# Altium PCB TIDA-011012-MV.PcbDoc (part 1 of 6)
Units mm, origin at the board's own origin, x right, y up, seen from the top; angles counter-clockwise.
Board outline 360 x 280 mm, 4 copper layers (Top Layer, Layer 1, Layer 2, Bottom Layer), stack 2.066 mm thick; 566 components, 345 nets, 1738 pads, 2486 vias.
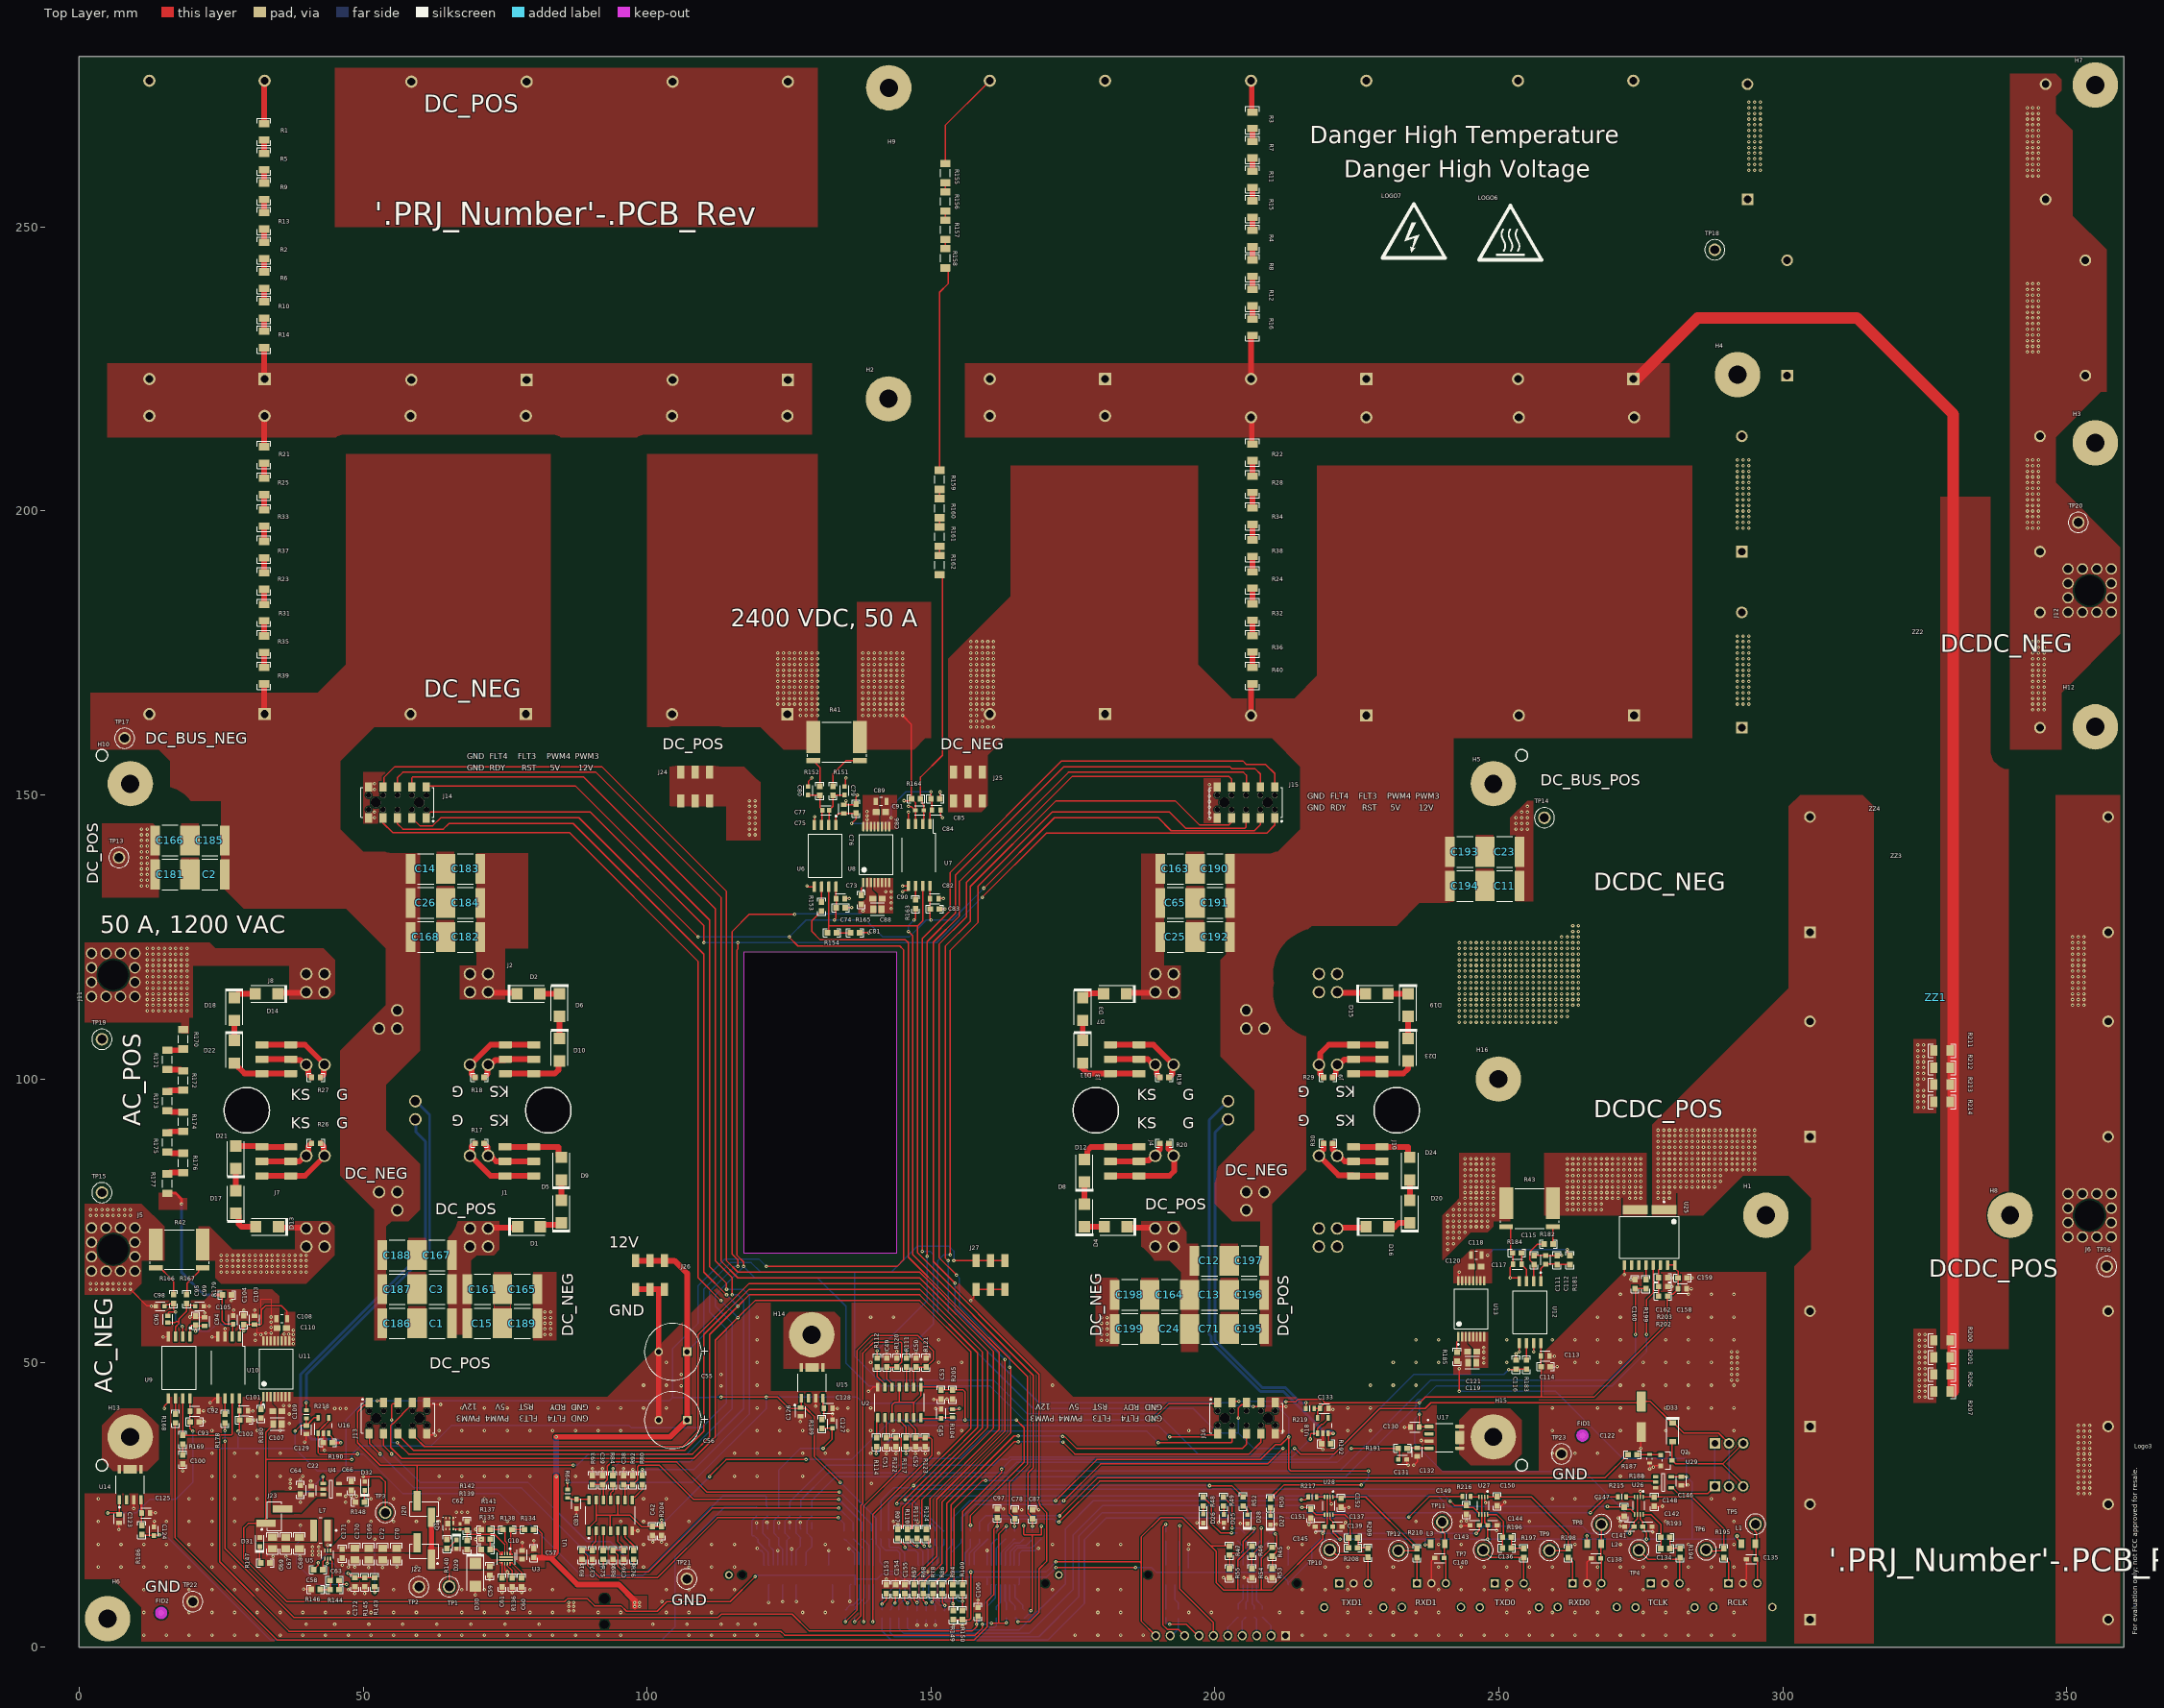
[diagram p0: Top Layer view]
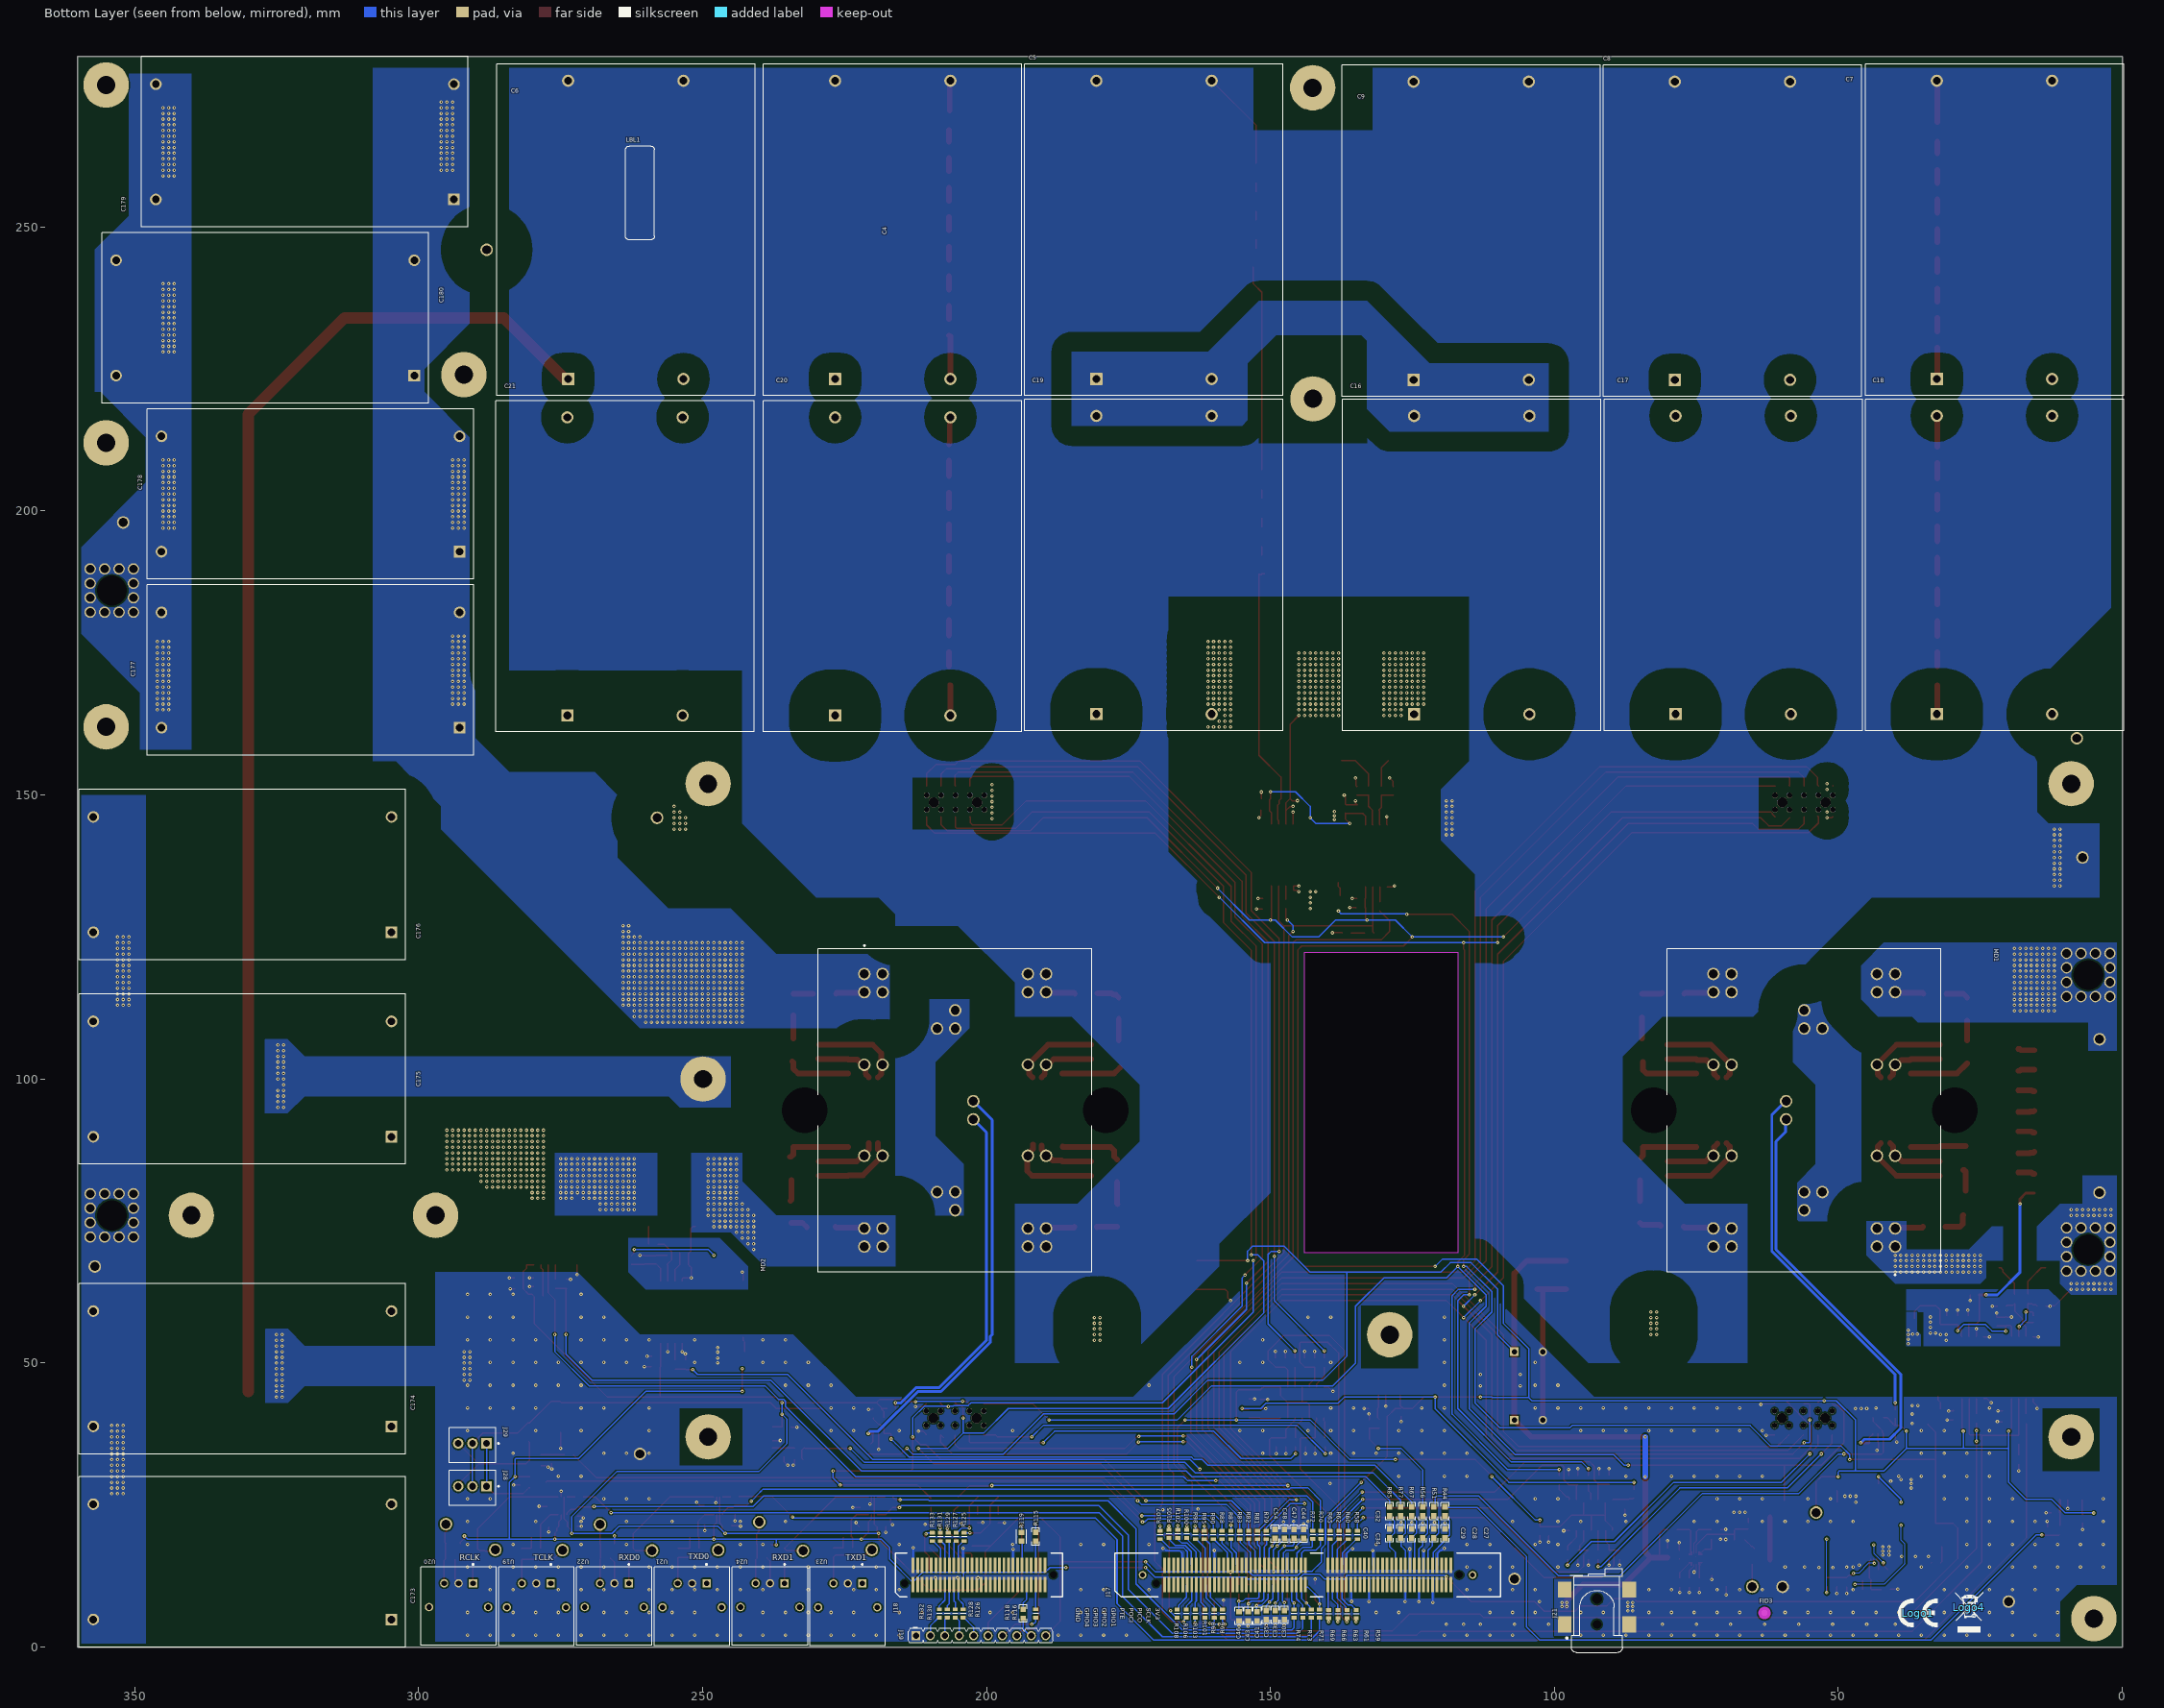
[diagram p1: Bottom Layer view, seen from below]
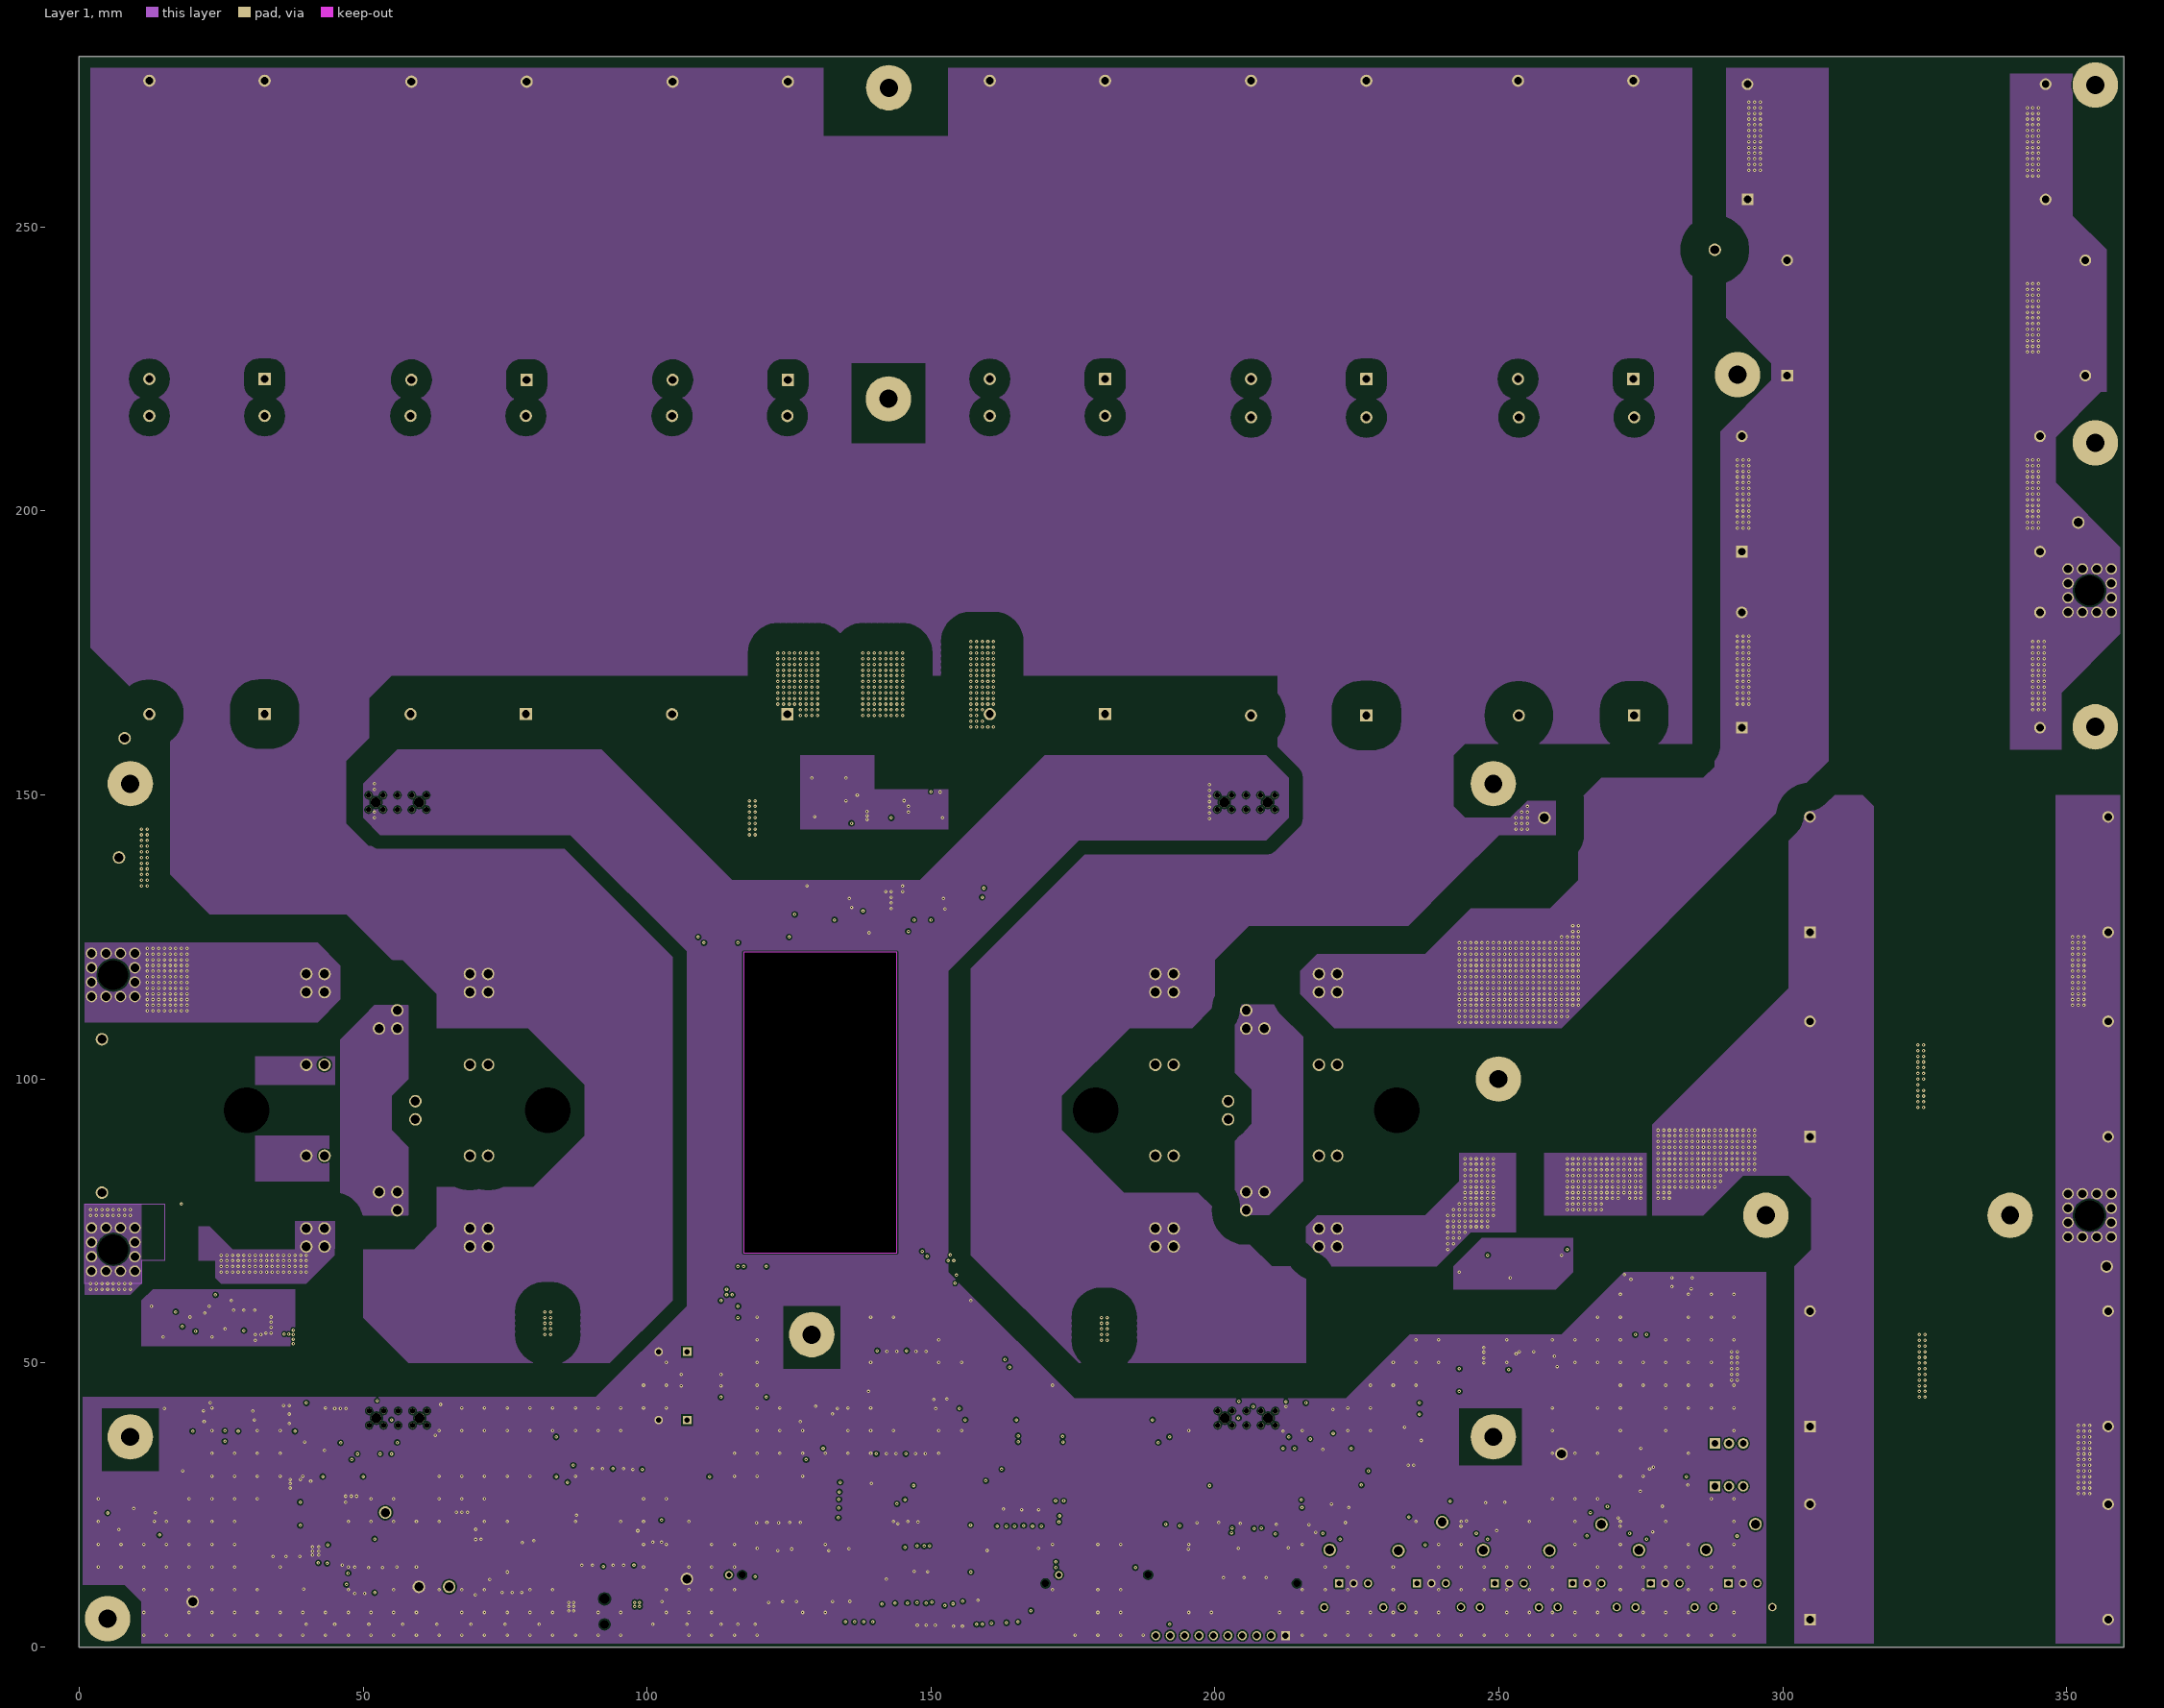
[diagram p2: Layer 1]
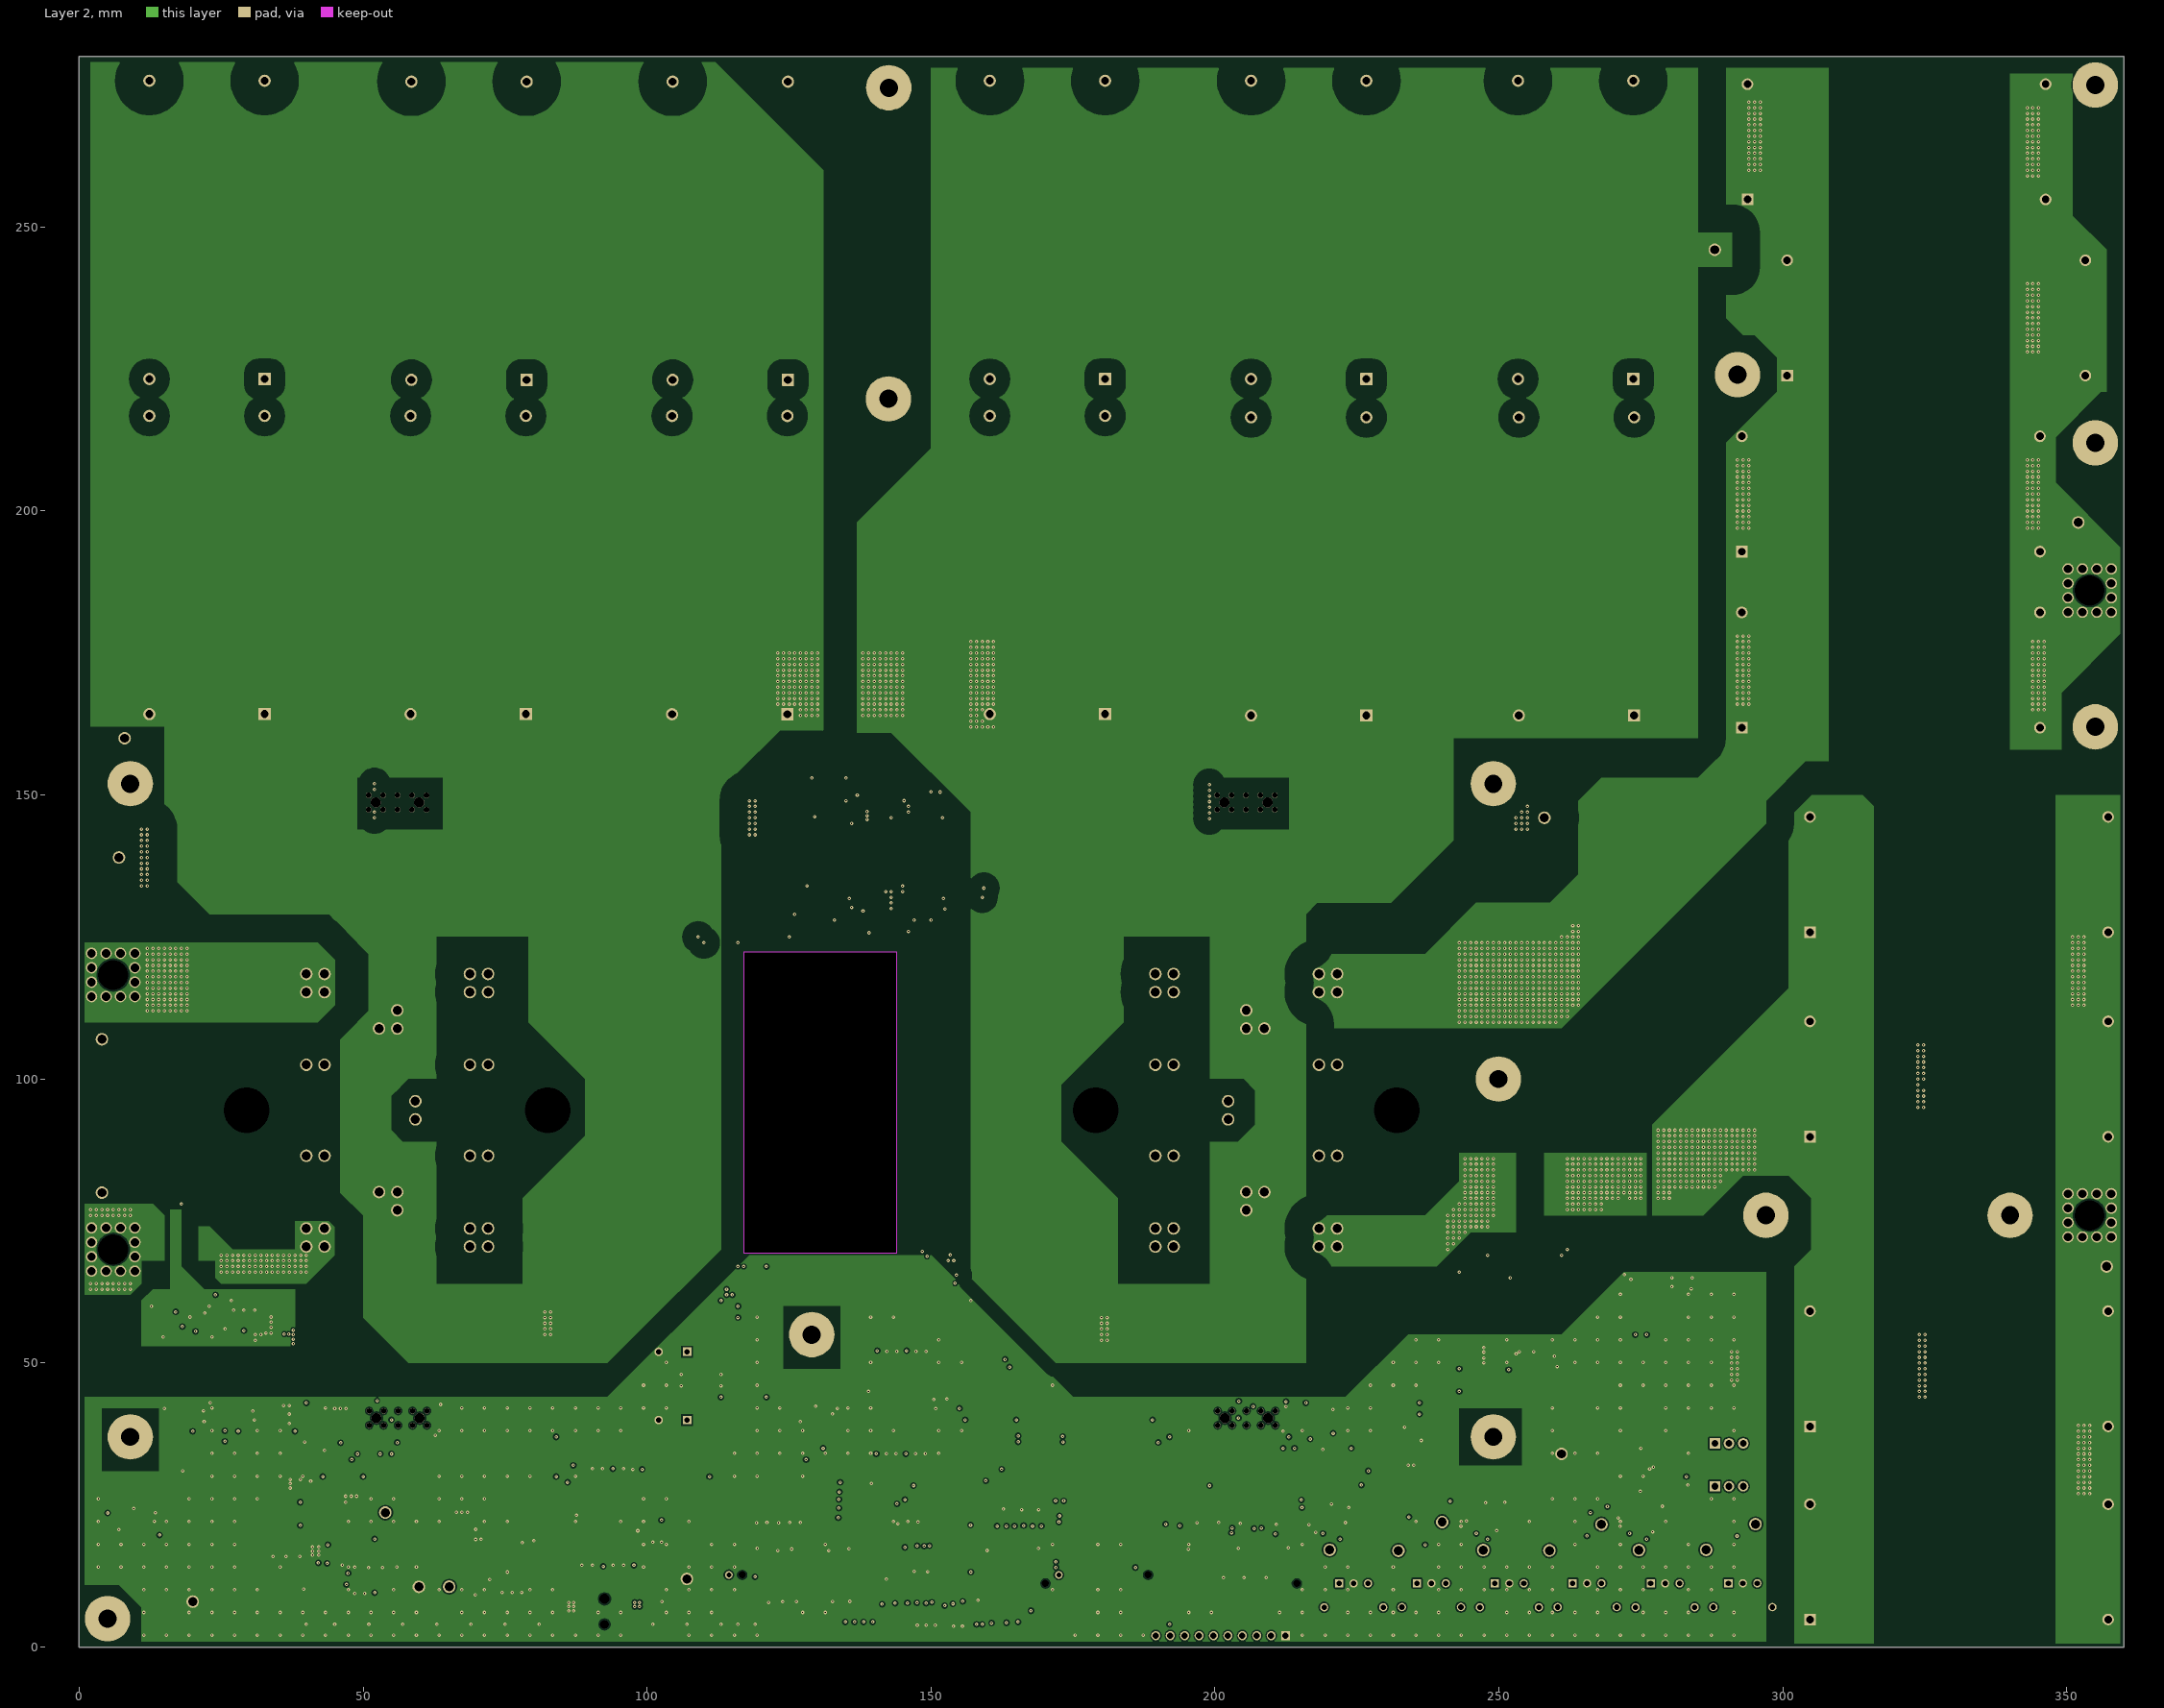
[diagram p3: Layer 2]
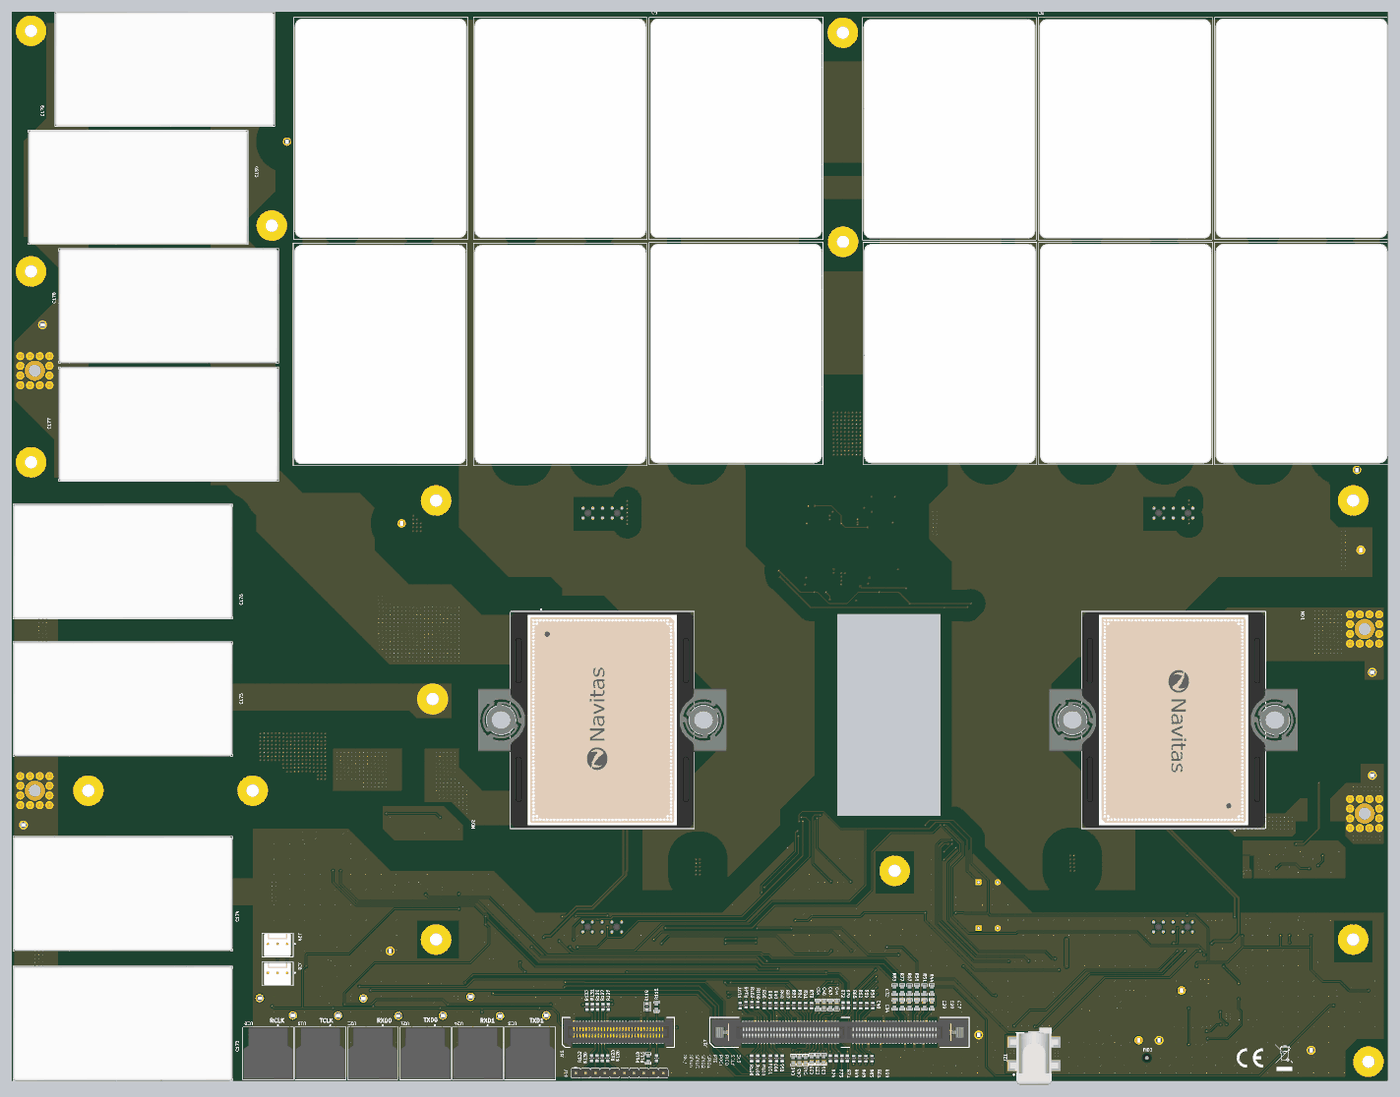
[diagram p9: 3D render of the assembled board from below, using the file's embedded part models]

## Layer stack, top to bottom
Top Solder: solder mask 0.0102, Solder Resist, Dk 3.5
Top Layer: signal copper 0.105
Dielectric 1: prepreg 0.0711, PP-006, Dk 4.1
Layer 1: signal copper 0.105
Dielectric1: core 1.5037, FR-4 High Tg, Dk 4.8
Layer 2: signal copper 0.105
Dielectric 2: prepreg 0.0711, PP-006, Dk 4.1
Bottom Layer: signal copper 0.105
Bottom Solder: solder mask 0.0102, Solder Resist, Dk 3.5

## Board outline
0,0 360,0 360,280 0,280
cut-out: 117,69.4 144,69.4 144,122.3 117,122.3

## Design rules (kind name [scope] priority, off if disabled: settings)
AcuteAngle [All] p1: minimum=4.50000000000000E+0001 checktracksonly=FALSE
AssemblyTestPointUsage [All] p1: valid=2
BoardOutlineClearance BoardOutlineClearance_MountingHoles [OnCopper and InComponentClass('Mounting Holes')] p1: gap=1 ignorepadtopadclearanceinfootprint=FALSE
BoardOutlineClearance BoardOutlineClearance_Poly [OnCopper and IsPoly] p2: gap=0.635 ignorepadtopadclearanceinfootprint=FALSE
BoardOutlineClearance [OnCopper and Not InComponentClass('Logo') and not InComponentClass('FiducialMark') and not InRegion(1000,500,4000,800) and not InPoly] p3: gap=1.016 ignorepadtopadclearanceinfootprint=FALSE
Clearance Clearance_HV_DC_P_OutLayer_A [InNetClass('HV_DC_P') and (OnLayer('Top Layer') or OnLayer('Bottom Layer') or OnLayer('Multi-Layer')) vs (InNetClass('HV_DC_N') OR InNetClass('HV_AC_N') OR InNetClass('HV_AC_P') OR InNetClass('HV_DC_SN_N') OR InNetClass('HV_DC_SN_P') )  and (OnLayer('Top Layer') or OnLayer('Bottom Layer') or OnLayer('Multi-Layer'))] p1: gap=7 ignorepadtopadclearanceinfootprint=TRUE
Clearance Clearance_HVM_OutLayer_A [InNetClass('HVM') and (OnLayer('Top Layer') or OnLayer('Bottom Layer') or OnLayer('Multi-Layer')) vs (InNetClass('HV_DC_N') OR InNetClass('HV_AC_N') OR InNetClass('HV_AC_P') OR InNetClass('HV_DC_SN_N') OR InNetClass('HV_DC_SN_P') OR InNetClass('HV_DC_P') )  and (OnLayer('Top Layer') or OnLayer('Bottom Layer') or OnLayer('Multi-Layer'))] p2: gap=3.5 ignorepadtopadclearanceinfootprint=TRUE
Clearance Clearance_HV_DC_N_OutLayer_A [InNetClass('HV_DC_N') and (OnLayer('Top Layer') or OnLayer('Bottom Layer') or OnLayer('Multi-Layer')) vs (InNetClass('HV_DC_P') OR InNetClass('HV_AC_N') OR InNetClass('HV_AC_P') OR InNetClass('HV_DC_SN_N') OR InNetClass('HV_DC_SN_P'))   and (OnLayer('Top Layer') or OnLayer('Bottom Layer') or OnLayer('Multi-Layer'))] p3: gap=7 ignorepadtopadclearanceinfootprint=TRUE
Clearance Clearance_HV_AC_N_OutLayer_A [InNetClass('HV_AC_N') and  (OnLayer('Top Layer') or OnLayer('Bottom Layer') or OnLayer('Multi-Layer')) vs (InNetClass('HV_DC_N') OR InNetClass('HV_DC_P') OR InNetClass('HV_AC_P') OR InNetClass('HV_DC_SN_N') OR InNetClass('HV_DC_SN_P')  )   and (OnLayer('Top Layer') or OnLayer('Bottom Layer') or OnLayer('Multi-Layer'))] p4: gap=7 ignorepadtopadclearanceinfootprint=TRUE
Clearance Clearance_HV_DC_SN_N_OutLayer_A [InNetClass('HV_DC_SN_N')  and (OnLayer('Top Layer') or OnLayer('Bottom Layer') or OnLayer('Multi-Layer')) vs (InNetClass('HV_DC_N') OR InNetClass('HV_DC_P') OR InNetClass('HV_AC_P') OR InNetClass('HV_AC_N') OR InNetClass('HV_DC_SN_P'))  and (OnLayer('Top Layer') or OnLayer('Bottom Layer') or OnLayer('Multi-Layer'))] p5: gap=7 ignorepadtopadclearanceinfootprint=TRUE
Clearance Clearance_HV_DC_SN_P_OutLayer_A [InNetClass('HV_DC_SN_P')  and (OnLayer('Top Layer') or OnLayer('Bottom Layer') or OnLayer('Multi-Layer')) vs (InNetClass('HV_DC_N') OR InNetClass('HV_DC_P') OR InNetClass('HV_AC_P') OR InNetClass('HV_DC_SN_N') OR InNetClass('HV_AC_N')) and  (OnLayer('Top Layer') or OnLayer('Bottom Layer') or OnLayer('Multi-Layer'))] p6: gap=7 ignorepadtopadclearanceinfootprint=TRUE
Clearance Clearance_HV_AC_P_OutLayer_A [InNetClass('HV_AC_P')       and (OnLayer('Top Layer') or OnLayer('Bottom Layer') or OnLayer('Multi-Layer')) vs (InNetClass('HV_DC_N') OR InNetClass('HV_DC_P') OR InNetClass('HV_AC_N') OR InNetClass('HV_DC_SN_N') OR InNetClass('HV_DC_SN_P'))   and (OnLayer('Top Layer') or OnLayer('Bottom Layer') or OnLayer('Multi-Layer'))] p7: gap=5 ignorepadtopadclearanceinfootprint=TRUE
Clearance Clearance_HV_DC_P_InnerLayers [InNetClass('HV_DC_P') vs InNetClass('HV_DC_N') OR InNetClass('HV_AC_N') OR InNetClass('HV_AC_P') OR InNetClass('HV_DC_SN_N') OR InNetClass('HV_DC_SN_P')] p8: gap=5 ignorepadtopadclearanceinfootprint=TRUE
Clearance Clearance_HVM_InnerLayers [InNetClass('HVM') vs (InNetClass('HV_DC_N') OR InNetClass('HV_AC_N') OR InNetClass('HV_AC_P') OR InNetClass('HV_DC_SN_N') OR InNetClass('HV_DC_SN_P') OR InNetClass('HV_DC_P') )] p9: gap=2.5 ignorepadtopadclearanceinfootprint=TRUE
Clearance Clearance_HV_DC_N_InnerLayers [InNetClass('HV_DC_N') vs InNetClass('HV_DC_P') OR InNetClass('HV_AC_N') OR InNetClass('HV_AC_P') OR InNetClass('HV_DC_SN_N') OR InNetClass('HV_DC_SN_P')] p10: gap=5 ignorepadtopadclearanceinfootprint=TRUE
Clearance Clearance_HV_AC_N_InnerLayers [InNetClass('HV_AC_N') vs InNetClass('HV_DC_N') OR InNetClass('HV_DC_P') OR InNetClass('HV_AC_P') OR InNetClass('HV_DC_SN_N') OR InNetClass('HV_DC_SN_P')] p11: gap=5 ignorepadtopadclearanceinfootprint=TRUE
Clearance Clearance_HV_AC_P_InnerLayers [InNetClass('HV_AC_P') vs InNetClass('HV_DC_N') OR InNetClass('HV_DC_P') OR InNetClass('HV_AC_N') OR InNetClass('HV_DC_SN_N') OR InNetClass('HV_DC_SN_P')] p12: gap=5 ignorepadtopadclearanceinfootprint=TRUE
Clearance Clearance_HV_DC_SN_N_InnerLayers [InNetClass('HV_DC_SN_N') vs InNetClass('HV_DC_N') OR InNetClass('HV_DC_P') OR InNetClass('HV_AC_P') OR InNetClass('HV_AC_N') OR InNetClass('HV_DC_SN_P')] p13: gap=5 ignorepadtopadclearanceinfootprint=TRUE
Clearance Clearance_HV_DC_SN_P_InnerLayers [InNetClass('HV_DC_SN_P') vs InNetClass('HV_DC_N') OR InNetClass('HV_DC_P') OR InNetClass('HV_AC_P') OR InNetClass('HV_DC_SN_N') OR InNetClass('HV_AC_N')] p14: gap=5 ignorepadtopadclearanceinfootprint=TRUE
Clearance Clearance_Keepouts [((IsTrack Or IsArc) And Not InPoly) And IsFree and IsKeepOut vs ((IsTrack Or IsArc) And Not InPoly) And IsFree and IsKeepOut] p15: gap=0 ignorepadtopadclearanceinfootprint=FALSE
Clearance Clearance_Poly [InPolygon] p16: gap=0.254 ignorepadtopadclearanceinfootprint=TRUE
Clearance Clearance_FiducialMark [IsKeepOut and InComponentClass('FiducialMark') vs IsPad and InComponentClass('FiducialMark')] p17: gap=0 ignorepadtopadclearanceinfootprint=FALSE
Clearance [All] p18: gap=0.2 ignorepadtopadclearanceinfootprint=TRUE
ComponentClearance ComponentClearance_MountingHoles_FiducialMarks [InComponentClass('Mounting Holes') vs InComponentClass('FiducialMark')] p1: gap=1.27 collisioncheckmode=3 verticalgap=0.254 showdistances=FALSE
ComponentClearance ComponentClearance_Shunt [InComponentClass('Header') vs InComponentClass('Shunt')] p2: gap=0 collisioncheckmode=3 verticalgap=0 showdistances=FALSE
ComponentClearance ComponentClearance_Logo [InComponentClass('Logo')] p3: gap=0.762 collisioncheckmode=3 verticalgap=0.254 showdistances=FALSE
ComponentClearance ComponentClearance_ScrewToNut [(HasFootprint('NY PMS 440 0025 PH')) vs (HasFootprint('Keystone_1902C'))] p4: gap=0.127 collisioncheckmode=3 verticalgap=0.254 showdistances=FALSE
ComponentClearance ComponentClearance_MountingHoles [InComponentClass('Mounting Holes')] p5: gap=2 collisioncheckmode=3 verticalgap=2540 showdistances=FALSE
ComponentClearance ComponentClearance_SmallPassives [HasFootprint('0201*') or HasFootprint('0402*') or HasFootprint('0508') or HasFootprint('0603*') or HasFootprint('0612') or HasFootprint('0805*') or HasFootprint('0815*') or HasFootprint('0830*') or HasFootprint('1206*') or HasFootprint('1210*') or HasFootprint('1808*') or HasFootprint('1812*') or HasFootprint('1825*') or HasFootprint('2010*') or HasFootprint('2220*') or HasFootprint('2225*') or HasFootprint('2512*') or HasFootprint('2728*') or HasFootprint('3518*') vs HasFootprint('0201*') or HasFootprint('0402*') or HasFootprint('0508') or HasFootprint('0603*') or HasFootprint('0612') or HasFootprint('0805*') or HasFootprint('0815*') or HasFootprint('0830*') or HasFootprint('1206*') or HasFootprint('1210*') or HasFootprint('1808*') or HasFootprint('1812*') or HasFootprint('1825*') or HasFootprint('2010*') or HasFootprint('2220*') or HasFootprint('2225*') or HasFootprint('2512*') or HasFootprint('2728*') or HasFootprint('3518*')] p6: gap=0.38 collisioncheckmode=3 verticalgap=0.254 showdistances=FALSE
ComponentClearance ComponentClearance_THtoSMT [IsThruComponent vs IsSMTComponent] p7: gap=0.762 collisioncheckmode=3 verticalgap=0.762 showdistances=FALSE
ComponentClearance ComponentClearance_THtoTH [IsThruComponent vs IsThruComponent] p8: gap=0.508 collisioncheckmode=3 verticalgap=0.762 showdistances=FALSE
ComponentClearance [All] p9: gap=0.508 collisioncheckmode=3 verticalgap=0.254 showdistances=FALSE
DiffPairsRouting [All] p1: maxlimit=2.54 minlimit=0.254 mostfreqgap=0.254 toplayer_minwidth=0.381 toplayer_maxwidth=0.381 toplayer_prefwidth=0.381 midlayer1_minwidth=0.381 midlayer1_maxwidth=0.381 midlayer1_prefwidth=0.381 midlayer2_minwidth=0.381 midlayer2_maxwidth=0.381 midlayer2_prefwidth=0.381 bottomlayer_minwidth=0.381 bottomlayer_maxwidth=0.381 bottomlayer_prefwidth=0.381 maxuncoupledlength=25.4
FabricationTestPointUsage TestPointUsage [All] p1: valid=2 allowmultiple=FALSE
FabricationTestpoint Testpoint [All] p1: side=3 testpointundercomponent=TRUE minsize=1.016 maxsize=2.54 preferedsize=1.524 minholesize=0 maxholesize=1.016 preferedholesize=0.813 testpointgrid=0.025 allowsidetop=TRUE allowsidebottom=TRUE usegrid=TRUE gridtolerance=0
FanoutControl Fanout_LCC [IsLCC] p1: bgadir=Out bgaviamode=Centered fanoutstyle=Auto fanoutdirection=Alternating viagrid=0.025 // Fanout_LCC (Default Rule)
FanoutControl Fanout_BGA [IsBGA] p2: bgadir=Out bgaviamode=Centered fanoutstyle=Auto fanoutdirection=Alternating viagrid=0.025 // Fanout_BGA (Default Rule)
FanoutControl Fanout_Default [All] p4: bgadir=Out bgaviamode=Centered fanoutstyle=Auto fanoutdirection=Alternating viagrid=0.025 // Fanout_Default (Default Rule)
FanoutControl Fanout_Small [(CompPinCount < 5)] p5: bgadir=Out bgaviamode=Centered fanoutstyle=Auto fanoutdirection=OutThenIn viagrid=0.025 // Fanout_Small (Default Rule)
HoleSize [All] p1: absolutevalues=TRUE maxlimit=6.375 minlimit=0.2 maxpercent=80.000 minpercent=20.000
MinimumAnnularRing MinimumAnnularRing_ThermalPadVias [IsVia and InAnyComponent] p1: minimumring=0.15
MinimumAnnularRing [All] p2: minimumring=0.2
MinimumSolderMaskSliver MinimumSolderMaskSliver_Logo [InComponentClass('Logo') vs InComponentClass('Logo')] p1: minsoldermaskwidth=0.018
MinimumSolderMaskSliver [All] p2: minsoldermaskwidth=0.1
PlaneConnect [All] p1: planeconnectstyle=Relief reliefexpansion=0.254 reliefentries=4 reliefconductorwidth=0.254 reliefairgap=0.254
PolygonConnect [All] p1: connectstyle=Direct reliefconductorwidth=0.254 reliefentries=4 polygonreliefangle="90 Angle" airgapwidth=0.254
RoutingLayers [All] p1: top layer_v5=TRUE mid layer 1_v5=FALSE mid layer 2_v5=FALSE bottom layer_v5=TRUE
RoutingVias ThermalPadVias [IsVia and InAnyComponent] p1: holewidth=0.2 width=0.5 viastyle="Through Hole" minholewidth=0.2 minwidth=0.5 maxholewidth=0.33 maxwidth=0.6
RoutingVias [All] p2: holewidth=0.406 width=0.864 viastyle="Through Hole" minholewidth=0.2 minwidth=0.61 maxholewidth=1.016 maxwidth=1.651 useviatemplates=TRUE viatemplateguid#1={116764BD-FC13-4FEF-98DC-B798B7858576} viatemplatename#1=v60h20m0mx0
SilkToBoardRegionClearance [Not ((IsComment or IsDesignator) And (Hide <> 'False')) and not InRegion(1000,500,4000,800)] p1:
SilkToSilkClearance SilkToSilkClearance_Pb-FreeLogo [(HasFootprint('Pb-Free_Overlay_Medium') OR HasFootprint('Pb-Free_Overlay_Small')) vs (HasFootprint('Pb-Free_Overlay_Medium') OR HasFootprint('Pb-Free_Overlay_Small'))] p1: silktosilkclearance=0
SilkToSilkClearance [All] p2: silktosilkclearance=0.1
SilkToSolderMaskClearance SilkToComponentPadClearance [(IsPad or IsFill or IsRegion) and InAnycomponent] p1: minsilkscreentomaskgap=0.127 clearancetoexposedcopper=TRUE
SilkToSolderMaskClearance "Silk to Solder Mask Opening" [All] p2: minsilkscreentomaskgap=0.1 clearancetoexposedcopper=FALSE
SolderMaskExpansion [All] p1: expansion=0.05 istentingtop=FALSE
UnRoutedNet [All] p1: checkbadconnections=TRUE
Width [All] p1: maxlimit=5 minlimit=0.2 preferedwidth=0.254 checkconnectedcopper=TRUE
13 further rules are at their usual default settings.

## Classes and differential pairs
net class HVM: 3V3 5V 12V 12V_FET_DRAIN 12V_IN 12V_OUT AC_BUF_PMW1 AC_BUF_PMW2 AC_BUF_PMW3 AC_BUF_PMW4 AC_FAULT_FET1 AC_FAULT_FET2 AC_FAULT_FET3 AC_FAULT_FET4 AC_GD_RDY AC_GD_RST/EN AC_PWM1 AC_PWM2 AC_PWM3 AC_PWM4 CLK_MOD_AC CLK_MOD_DC DATA_I_AC DATA_I_DC DATA_V_AC DATA_V_DC DC_BUF_PMW1 DC_BUF_PMW2 DC_BUF_PMW3 DC_BUF_PMW4 DC_FAULT_FET1 DC_FAULT_FET2 DC_FAULT_FET3 DC_FAULT_FET4 DC_GD_RDY DC_GD_RST/EN DC_OC DC_OC_CMP DC_PWM1 DC_PWM2 DC_PWM3 DC_PWM4 DEBUG_GPIO1 DEBUG_GPIO2 DEBUG_GPIO3 DEBUG_GPIO4 EF_dVdt EF_EN EF_ILIM EF_ITIMER EF_OVLO EF_PG EF_PGTH FAN_EN FAN_PWM FSIRXA_CLK FSIRXA_D0 FSITXA_CLK FSITXA_D0 GND I_HALL ID1 ID2 ID3 LED_GREEN LED_RED NetC4_1 NetC22_1 NetC27_1 NetC28_1 NetC29_1 NetC30_1 NetC31_2 NetC32_1 NetC33_1 NetC34_1 NetC35_1 NetC40_1 NetC41_1 NetC43_1 NetC44_1 NetC45_2 NetC46_1 NetC47_1 NetC48_1 NetC54_1 NetC58_1 NetC58_2 NetC63_2 NetC70_1 NetC81_1 NetC100_1 NetC125_1 NetC128_1 NetC132_1 NetC134_1 NetC135_2 NetC136_1 NetC138_2 NetC139_1 NetC140_2 NetC153_1 NetC154_1 NetC155_1 NetC162_1 NetC172_1 NetD25_2 NetD26_2 NetD27_2 NetD28_2 NetD29_1 NetD31_1 NetD32_1 NetD33_2 NetH13_1 NetH14_1 NetH15_1 NetH16_1 NetJ17_3 NetJ17_4 NetJ17_5 NetJ17_6 NetJ17_8 NetJ17_12 NetJ17_14 NetJ17_18 NetJ17_20 NetJ17_23 NetJ17_24 NetJ17_26 NetJ17_27 NetJ17_28 NetJ17_29 NetJ17_30 NetJ17_31 NetJ17_32 NetJ17_33 NetJ17_34 NetJ17_36 NetJ17_37 NetJ17_39 NetJ17_40 NetJ17_41 NetJ17_42 NetJ17_43 NetJ17_44 NetJ17_45 NetJ17_49 NetJ17_50 NetJ17_51 NetJ17_52 NetJ17_53 NetJ17_54 NetJ17_55 NetJ17_56 NetJ17_57 NetJ17_59 NetJ17_61 NetJ17_62 NetJ17_63 NetJ17_66 NetJ17_75 NetJ17_77 NetJ17_79 NetJ17_80 NetJ17_81 NetJ17_82 NetJ17_85 NetJ17_86 NetJ17_87 NetJ17_88 NetJ17_89 NetJ17_90 NetJ17_91 NetJ17_92 NetJ17_93 NetJ17_94 NetJ17_95 NetJ17_96 NetJ17_99 NetJ17_100 NetJ17_101 NetJ17_102 NetJ17_103 NetJ17_104 NetJ17_105 NetJ17_106 NetJ17_107 NetJ17_108 NetJ17_109 NetJ17_110 NetJ17_113 NetJ17_114 NetJ17_115 NetJ17_116 NetJ17_117 NetJ17_118 NetJ17_119 NetJ17_120 NetJ18_121 NetJ18_122 NetJ18_123 NetJ18_124 NetJ18_125 NetJ18_126 NetJ18_127 NetJ18_128 NetJ18_129 NetJ18_130 NetJ18_131 NetJ18_132 NetJ18_133 NetJ18_134 NetJ18_136 NetJ18_137 NetJ18_138 NetJ18_139 NetJ18_140 NetJ18_141 NetJ18_142 NetJ18_143 NetJ18_144 NetJ18_145 NetJ18_146 NetJ18_147 NetJ18_148 NetJ18_149 NetJ18_150 NetJ18_151 NetJ18_152 NetJ18_153 NetJ18_154 NetJ18_155 NetJ18_156 NetJ18_159 NetJ18_160 NetJ18_161 NetJ18_162 NetJ18_163 NetJ18_164 NetJ18_165 NetJ18_166 NetJ18_167 NetJ18_168 NetJ18_169 NetJ18_170 NetJ18_171 NetJ18_172 NetJ18_173 NetJ18_174 NetJ18_175 NetJ18_176 NetJ18_177 NetJ18_178 NetJ28_1 NetQ2_1 NetR75_1 NetR76_1 NetR80_1 NetR84_1 NetR111_1 NetR112_1 NetR114_1 NetR117_1 NetR153_1 NetR163_1 NetR165_1 NetR168_1 NetR178_1 NetR180_1 NetR183_1 NetR185_1 NetR194_2 NetR195_1 NetR197_2 NetR198_1 NetR199_1 NetR209_2 NetR210_1 NetR215_2 NetR216_2 NetR217_2 NetU19_4 NetU19_5 NetU20_4 NetU20_5 NetU21_4 NetU21_5 NetU22_4 NetU22_5 NetU23_4 NetU23_5 NetU24_4 NetU24_5 NetU25_4 NetU25_5 NTC1_N NTC1_P NTC2_N NTC2_P PWM_BUF_EN PWM_CLK_SD_AC_DELAYED PWM_CLK_SD_DC_DELAYED PWM_SYNC_RX PWM_SYNC_TX RXCLK_5V RXD0_5V RXD1_5V SPIB_CLK SPIB_PICO SPIB_POCI SPIB_PTE TEMP1 TEMP2 TEMP3 TEMP4 TEMP5 TXCLK_5V TXD0_5V TXD1_5V
net class HV_DC_SN_N: DC_DS1 DC_G1 DC_KS1 NetC177_1 NetC177_2
net class HV_AC_P: AC_DS3 AC_G3 AC_KS3 VAC_POS
net class HV_AC_N: 5V_ISO_AC_SENS AC_DS1 AC_G1 AC_KS1 GND_ISO_AC_SENS IAC_NEG IAC_POS NetC96_1 NetC96_2 NetC105_2 NetD13_1
net class HV_DC_SN_P: 5V_ISO_SN_SENS DC_DS3 DC_G3 DC_KS3 I_HALL_N I_HALL_P I_SW_NEG I_SW_POS NetC111_1 NetC115_1 NetC117_1 NetC173_2 NetD16_1
net class HV_DC_P: DC_BUS_POS
net class HV_DC_N: AC_DS2 AC_G2 AC_G4 AC_KS2 AC_KS4 DC_BUS_DAB DC_BUS_NEG DC_DS2 DC_DS4 DC_G2 DC_G4 DC_KS2 DC_KS4 NetD22_2
component class "U_TIDA-011012 Switch Node Hall Current Sensing": C158 C159 C160 C162 R199 R202 R203 U25
component class "U_TIDA-011012 DC IV Sensing": C73 C74 C75 C76 C77 C78 C79 C80 C81 C82 C83 C84 C85 C86 C87 C88 C89 C90 C91 R151 R152 R153 R154 R155 R156 R157 R158 R159 R160 R161 R162 R163 R164 R165 U6 U7 U8
component class U_TIDA-011012_Hardware: !PCB1 FID1 FID2 FID3 H1 H2 H3 H4 H5 H6 H7 H8 H9 H10 H12 LBL1 Logo1 Logo3 Logo4 LOGO6 LOGO7 ZZ1 ZZ2 ZZ3 ZZ4
component class Label: LBL1
component class FiducialMark: FID1 FID2 FID3
component class AssemblyNote: ZZ1 ZZ2 ZZ3 ZZ4
component class "U_TIDA-011012 Optical Interface": C134 C135 C136 C137 C138 C139 C140 C141 C142 C143 C144 C145 C147 C148 C149 C150 C151 C152 L1 L2 L3 R193 R194 R195 R196 R197 R198 R208 R209 R210 R215 R216 R217 TP4 TP5 TP6 TP7 TP8 TP9 TP10 TP11 TP12 U19 U20 U21 U22 U23 U24 U26 U27 U28
component class "U_TIDA-011012 Fans and Temp Sense": C122 C123 C124 C125 C126 C127 C128 C129 C130 C131 C132 C133 C146 D33 H13 H14 H15 J28 J29 Q2 R186 R187 R188 R189 R190 R191 R192 R218 R219 U14 U15 U16 U17 U18 U29
component class "U_TIDA-011012 AC IV Sensing": C92 C93 C94 C95 C96 C97 C98 C99 C100 C101 C102 C103 C104 C105 C106 C107 C108 C109 C110 R166 R167 R168 R169 R170 R171 R172 R173 R174 R175 R176 R177 R178 R179 R180 U9 U10 U11
component class "U_TIDA-011012 Communication": C27 C28 C29 C30 C31 C32 C33 C34 C35 C36 C37 C38 C39 C40 C41 C42 C43 C44 C45 C46 C47 C48 C49 C50 C51 C52 C53 C54 C153 C154 C155 D25 D26 D27 D28 J17 J18 J19 R44 R45 R46 R47 R48 R49 R50 R51 R52 R53 R54 R55 R56 R57 R58 R59 R60 R61 R62 R63 R64 R65 R66 R67 R68 R69 R70 R71 R72 R73 R74 R75 R76 R77 R78 R79 R80 R81 R82 R83 R84 R85 R86 R87 R88 R89 R90 R91 R92 R93 R94 R95 R96 R97 R98 R99 R100 R101 R102 R103 R104 R105 R106 R107 R108 R109 R110 R111 R112 R113 R114 R115 R116 R117 R118 R119 R120 R121 R122 R123 R124 R125 R126 R127 R128 R129 R130 R131 R132 R133 R149 R150 R204 R205 U1 U2
component class "U_TIDA-011012 Current Comparator": C111 C112 C113 C114 C115 C116 C117 C118 C119 C120 C121 R181 R182 R183 R184 R185 U12 U13
component class "TIDA-011012-MV Power Conversion": C1 C2 C3 C4 C5 C6 C7 C8 C9 C11 C12 C13 C14 C15 C16 C17 C18 C19 C20 C21 C23 C24 C25 C26 C65 C71 C161 C163 C164 C165 C166 C167 C168 C173 C174 C175 C176 C177 C178 C179 C180 C181 C182 C183 C184 C185 C186 C187 C188 C189 C190 C191 C192 C193 C194 C195 C196 C197 C198 C199 D1 D2 D3 D4 D5 D6 D7 D8 D9 D10 D11 D12 D13 D14 D15 D16 D17 D18 D19 D20 D21 D22 D23 D24 H16 J1 J2 J3 J4 J5 J6 J7 J8 J9 J10 J11 J12 J13 J14 J15 J16 MD1 MD2 R1 R2 R3 R4 R5 R6 R7 R8 R9 R10 R11 R12 R13 R14 R15 R16 R17 R18 R19 R20 R21 R22 R23 R24 R25 R26 R27 R28 R29 R30 R31 R32 R33 R34 R35 R36 R37 R38 R39 R40 R41 R42 R43 R200 R201 R206 R207 R211 R212 R213 R214 TP13 TP14 TP15 TP16 TP17 TP18 TP19 TP20
component class Header: J19 J20 J22 J23
component class "U_TIDA-011012 Auxiliary Power": C10 C22 C55 C56 C57 C58 C59 C60 C61 C62 C63 C64 C66 C67 C68 C69 C70 C72 C169 C170 C171 C172 D29 D30 D31 D32 J20 J21 J22 J23 J24 J25 J26 J27 L7 Q1 R134 R135 R136 R137 R138 R139 R140 R141 R142 R143 R144 R145 R146 R147 R148 TP1 TP2 TP3 TP21 TP22 TP23 U3 U4 U5
component class "Mounting Holes": H1 H2 H3 H4 H5 H6 H7 H8 H9 H10 H12 H13 H14 H15 H16

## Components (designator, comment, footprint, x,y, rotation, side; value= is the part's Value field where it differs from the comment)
C1 "C2220X103KHRAC7800" FP-C2220X103KHRAC7800_2220-MFG 63,57 r0 top value=10nF
C2 "C2220X103KHRAC7800" FP-C2220X103KHRAC7800_2220-MFG 23,136 r180 top value=10nF
C3 "C2220X103KHRAC7800" FP-C2220X103KHRAC7800_2220-MFG 63,63 r0 top value=10nF
C4 "C4AQPEW5450M3BJ" FP-C4AQPEW5450M3BJ_RADIAL-MFG 216.5,249.5 r90 bottom locked value=45µF
C5 "C4AQPEW5450M3BJ" FP-C4AQPEW5450M3BJ_RADIAL-MFG 170.5,249.5 r90 bottom value=45µF
C6 "C4AQPEW5450M3BJ" FP-C4AQPEW5450M3BJ_RADIAL-MFG 263.5,249.5 r90 bottom locked value=45µF
C7 "C4AQPEW5450M3BJ" FP-C4AQPEW5450M3BJ_RADIAL-MFG 22.5,249.5 r90 bottom locked value=45µF
C8 "C4AQPEW5450M3BJ" FP-C4AQPEW5450M3BJ_RADIAL-MFG 68.65,249.35 r90 bottom locked value=45µF
C9 "C4AQPEW5450M3BJ" FP-C4AQPEW5450M3BJ_RADIAL-MFG 114.65,249.35 r90 bottom locked value=45µF
C10 "CL10B104KA8VPJC" FP-CL10B104KA8VPJC_0603-MFG 78,16.245 r90 top value=100nF
C11 "C2220X103KHRAC7800" FP-C2220X103KHRAC7800_2220-MFG 251,134 r0 top value=10nF
C12 "C2220X103KHRAC7800" FP-C2220X103KHRAC7800_2220-MFG 199,68 r180 top value=10nF
C13 "C2220X103KHRAC7800" FP-C2220X103KHRAC7800_2220-MFG 199,62 r180 top value=10nF
C14 "C2220X103KHRAC7800" FP-C2220X103KHRAC7800_2220-MFG 61,137 r0 top value=10nF
C15 "C2220X103KHRAC7800" FP-C2220X103KHRAC7800_2220-MFG 71,57 r180 top value=10nF
C16 "C4AQPEW5450M3BJ" FP-C4AQPEW5450M3BJ_RADIAL-MFG 114.542,190.483 r90 bottom locked value=45µF
C17 "C4AQPEW5450M3BJ" FP-C4AQPEW5450M3BJ_RADIAL-MFG 68.5,190.5 r90 bottom locked value=45µF
C18 "C4AQPEW5450M3BJ" FP-C4AQPEW5450M3BJ_RADIAL-MFG 22.5,190.5 r90 bottom locked value=45µF
C19 "C4AQPEW5450M3BJ" FP-C4AQPEW5450M3BJ_RADIAL-MFG 170.5,190.5 r90 bottom value=45µF
C20 "C4AQPEW5450M3BJ" FP-C4AQPEW5450M3BJ_RADIAL-MFG 216.5,190.25 r90 bottom locked value=45µF
C21 "C4AQPEW5450M3BJ" FP-C4AQPEW5450M3BJ_RADIAL-MFG 263.65,190.25 r90 bottom locked value=45µF
C22 "CL10B104KA8VPJC" FP-CL10B104KA8VPJC_0603-MFG 40.844,27.576 r90 top value=100nF
C23 "C2220X103KHRAC7800" FP-C2220X103KHRAC7800_2220-MFG 251,140 r0 top value=10nF
C24 "C2220X103KHRAC7800" FP-C2220X103KHRAC7800_2220-MFG 192,56 r0 top value=10nF
C25 "C2220X103KHRAC7800" FP-C2220X103KHRAC7800_2220-MFG 193,125 r180 top value=10nF
C26 "C2220X103KHRAC7800" FP-C2220X103KHRAC7800_2220-MFG 61,131 r0 top value=10nF
C27 "C0603X221K5RACTU" 0603 119.25,20 r90 bottom value=220pF
C28 "C0603X221K5RACTU" 0603 121.2,20 r90 bottom value=220pF
C29 "C0603X221K5RACTU" 0603 123.15,20 r90 bottom value=220pF
C30 "C0603X221K5RACTU" 0603 147.522,5.621 r270 bottom value=220pF
C31 "GMC10X7R104K25NT" FP-GMC10X7R104K25NT_0603-MFG 87.546,25.184 r90 top value=100nF
C32 "C0603X221K5RACTU" 0603 125.1,20 r90 bottom value=220pF
C33 "C0603X221K5RACTU" 0603 149.122,5.621 r270 bottom value=220pF
C34 "C0603X221K5RACTU" 0603 127.05,20 r90 bottom value=220pF
C35 "C0603X221K5RACTU" 0603 150.722,5.621 r270 bottom value=220pF
C36 "C0603X221K5RACTU" 0603 95.844,16.234 r90 top value=220pF
C37 "C0603X221K5RACTU" 0603 90.392,16.234 r90 top value=220pF
C38 "C0603X221K5RACTU" 0603 95.842,29.384 r270 top value=220pF
C39 "C0603X221K5RACTU" 0603 92.176,29.409 r270 top value=220pF
C40 "C0603X221K5RACTU" 0603 129,20 r90 bottom value=220pF
C41 "C0603X221K5RACTU" 0603 152.322,5.421 r270 bottom value=220pF
C42 "C0603X221K5RACTU" 0603 100.962,20.432 r90 top value=220pF
C43 "C0603X221K5RACTU" 0603 153.922,5.421 r270 bottom value=220pF
C44 "C0603X221K5RACTU" 0603 144.164,19.898 r90 bottom value=220pF
C45 "GMC10X7R104K25NT" FP-GMC10X7R104K25NT_0603-MFG 151.773,41.075 r270 top value=100nF
C46 "C0603X221K5RACTU" 0603 155.522,5.421 r270 bottom value=220pF
C47 "C0603X221K5RACTU" 0603 145.836,19.898 r90 bottom value=220pF
C48 "C0603X221K5RACTU" 0603 147.508,19.898 r90 bottom value=220pF
C49 "C0603X221K5RACTU" 0603 142.233,50.075 r270 top value=220pF
C50 "C0603X221K5RACTU" 0603 147.387,50.075 r270 top value=220pF
C51 "C0603X221K5RACTU" 0603 142.117,36.075 r90 top value=220pF
C52 "C0603X221K5RACTU" 0603 147.271,36.075 r90 top value=220pF
C53 "C0603X221K5RACTU" 0603 151.773,44.458 r90 top value=220pF
C54 "C0603X221K5RACTU" 0603 149.18,19.898 r90 bottom value=220pF
C55 "16ZLJ1000MCE10X16" CAPPR5-10x16 104.537,51.989 r180 top value=1000uF
C56 "16ZLJ1000MCE10X16" CAPPR5-10x16 104.537,39.966 r180 top value=1000uF
C57 "C1608X7R1V105K080AC" 0603 80.071,16.574 r90 top value=1uF
C58 "06033C104JAT2A" 0603 42.109,13.62 r180 top value=0.1uF
C59 "C1608X7R1V105K080AC" 0603 72.303,13.443 r270 top value=1uF
C60 "GRM188R72A272KA01D" 0603 77.897,11.376 r270 top value=2700pF
C61 "C0603X332K5RACTU" 0603 74.46,11.361 r270 top value=3300pF
C62 "GRM155R71E104KE14D" 0402L 67.071,21.214 r90 top value=0.1uF
C63 "GRM1885C2A220JA01D" 0603 44.943,11.748 r180 top value=22pF
C64 "EMK107BB7225KA-T" 0603 38.943,27.665 r90 top value=2.2uF
C65 "C2220X103KHRAC7800" FP-C2220X103KHRAC7800_2220-MFG 193,131 r180 top value=10nF
C66 "EMK107BB7225KA-T" 0603 47.895,28.356 r270 top value=2.2uF
C67 "GRM21BZ71A226ME15L" 0805_HV 36.375,18.281 r270 top value=22uF
C68 "GRM21BZ71A226ME15L" 0805_HV 38.781,18.281 r270 top value=22uF
C69 "GRM21BZ71A226ME15L" 0805_HV 34.034,18.281 r270 top value=22uF
C70 "EMK212BB7106KG-T" 0805_HV 55.905,16.406 r270 top value=10uF
C71 "C2220X103KHRAC7800" FP-C2220X103KHRAC7800_2220-MFG 199,56 r180 top value=10nF
C72 "EMK212BB7106KG-T" 0805_HV 53.452,16.406 r270 top value=10uF
C73 "CL10B104KA8VPJC" FP-CL10B104KA8VPJC_0603-MFG 134.044,131.764 r0 top value=100nF
C74 "CC0603KRX7R7BB225" 0603 134.094,130.142 r0 top value=2.2uF
C75 "CL10B104KA8VPJC" FP-CL10B104KA8VPJC_0603-MFG 134.655,147.533 r90 top value=100nF
C76 "CC0603KRX7R7BB225" 0603 136.816,147.633 r90 top value=2.2uF
C77 "C0603C103J3GAC7867" FP-C0603C103J3GAC7867_0603-MFG 131.483,147.313 r0 top value=10nF
C78 "0603ZC100KAT2A" 0603 164.77,23.385 r90 top value=10pF
C79 "0603ZC102KAT2A" FP-0603ZC102KAT2A_0603-MFG 134.749,150.763 r270 top value=1nF
C80 "0603ZC102KAT2A" FP-0603ZC102KAT2A_0603-MFG 128.366,150.763 r270 top value=1nF
C81 "C0603X221K5RACTU" 0603 136.606,125.741 r0 top value=220pF
C82 "CL10B104KA8VPJC" FP-CL10B104KA8VPJC_0603-MFG 150.596,131.764 r0 top value=100nF
C83 "CC0603KRX7R7BB225" 0603 150.646,129.933 r0 top value=2.2uF
C84 "CL10B104KA8VPJC" FP-CL10B104KA8VPJC_0603-MFG 150.905,147.351 r0 top value=100nF
C85 "CC0603KRX7R7BB225" 0603 150.782,149.353 r0 top value=2.2uF
C86 "06031C101JAT2A" FP-06031C101JAT2A_0603-MFG 147.986,147.313 r0 top value=100pF
C87 "0603ZC100KAT2A" 0603 167.863,23.385 r90 top value=10pF
C88 "MA0805XR106K160" FP-MA0805XR106K160_0805-IPC_C 140.551,129.933 r180 top value=10µF
C89 "GRT21BD71A226ME13L" FP-GRT21BD71A226ME13L_0805-MFG 141.198,148.888 r0 top value=22µF
C90 "C0603C153K5RACTU" FP-C0603C153K5RACTU_0603-IPC_A 140.583,131.764 r0 top
C91 "C0603C153K5RACTU" FP-C0603C153K5RACTU_0603-IPC_A 141.174,147 r180 top
C92 "CL10B104KA8VPJC" FP-CL10B104KA8VPJC_0603-MFG 20.296,41.547 r0 top value=100nF
C93 "CC0603KRX7R7BB225" 0603 20.344,39.653 r0 top value=2.2uF
C94 "CL10B104KA8VPJC" FP-CL10B104KA8VPJC_0603-MFG 22.1,57.3 r90 top value=100nF
C95 "CC0603KRX7R7BB225" 0603 20.497,57.491 r90 top value=2.2uF
C96 "C0603C103J3GAC7867" FP-C0603C103J3GAC7867_0603-MFG 15.6,57.7 r90 top value=10nF
C97 "0603ZC100KAT2A" 0603 161.63,23.57 r90 top value=10pF
C98 "0603ZC102KAT2A" FP-0603ZC102KAT2A_0603-MFG 14.25,60 r0 top value=1nF
C99 "0603ZC102KAT2A" FP-0603ZC102KAT2A_0603-MFG 21.2,60 r180 top value=1nF
C100 "C0603X221K5RACTU" 0603 18.235,33 r270 top value=220pF
C101 "CL10B104KA8VPJC" FP-CL10B104KA8VPJC_0603-MFG 28.98,41.637 r0 top value=100nF
C102 "CC0603KRX7R7BB225" 0603 29.03,39.949 r0 top value=2.2uF
C103 "CL10B104KA8VPJC" FP-CL10B104KA8VPJC_0603-MFG 30.86,57.546 r90 top value=100nF
C104 "CC0603KRX7R7BB225" 0603 28.98,57.546 r90 top value=2.2uF
C105 "06031C101JAT2A" FP-06031C101JAT2A_0603-MFG 27.1,57.6 r270 top value=100pF
C106 "0603ZC100KAT2A" 0603 158.247,6.19 r90 top value=10pF
C107 "MA0805XR106K160" FP-MA0805XR106K160_0805-IPC_C 34.917,39.284 r180 top value=10µF
C108 "GRT21BD71A226ME13L" FP-GRT21BD71A226ME13L_0805-MFG 35.675,57.812 r0 top value=22µF
C109 "C0603C153K5RACTU" FP-C0603C153K5RACTU_0603-IPC_A 34.9,41.533 r0 top
C110 "C0603C153K5RACTU" FP-C0603C153K5RACTU_0603-IPC_A 35.675,56.175 r180 top
C111 "CL10B104KA8VPJC" FP-CL10B104KA8VPJC_0603-MFG 258.224,68.167 r90 top value=100nF
C112 "CC0603KRX7R7BB225" 0603 260.223,68.122 r90 top value=2.2uF
C113 "CL10B104KA8VPJC" FP-CL10B104KA8VPJC_0603-MFG 258.125,51.228 r0 top value=100nF
C114 "CC0603KRX7R7BB225" 0603 258.224,49.38 r0 top value=2.2uF
C115 "C0603C274K8RACTU" 0603 256.213,68.127 r90 top value=0.27uF
C116 "0603ZC100KAT2A" 0603 253.017,49.728 r90 top value=10pF
C117 "CL10B104KA8VPJC" FP-CL10B104KA8VPJC_0603-MFG 253.245,67.4 r180 top value=100nF
C118 "GRT21BD71A226ME13L" FP-GRT21BD71A226ME13L_0805-MFG 246,69 r0 top value=22µF
C119 "MA0805XR106K160" FP-MA0805XR106K160_0805-IPC_C 245.282,50.105 r180 top value=10µF
C120 "C0603C153K5RACTU" FP-C0603C153K5RACTU_0603-IPC_A 246,67 r180 top
C121 "C0603C153K5RACTU" FP-C0603C153K5RACTU_0603-IPC_A 245.282,52 r0 top
C122 "UWT1E101MCL1GS" UWT_630x770 275.075,40.526 r270 top value=100uF
C123 "CL10B104KA8VPJC" FP-CL10B104KA8VPJC_0603-MFG 7.005,22.602 r270 top value=100nF
C124 "06031C101JAT2A" FP-06031C101JAT2A_0603-MFG 13.166,20.39 r270 top value=100pF
C125 "CL10B104KA8VPJC" FP-CL10B104KA8VPJC_0603-MFG 11.749,23.59 r0 top value=100nF
C126 "CL10B104KA8VPJC" FP-CL10B104KA8VPJC_0603-MFG 127,41.4 r270 top value=100nF
C127 "06031C101JAT2A" FP-06031C101JAT2A_0603-MFG 132.614,39.295 r270 top value=100pF
C128 "CL10B104KA8VPJC" FP-CL10B104KA8VPJC_0603-MFG 131.882,42.022 r0 top value=100nF
C129 "CL10B104KA8VPJC" FP-CL10B104KA8VPJC_0603-MFG 40,38.245 r270 top value=100nF
C130 "CL10B104KA8VPJC" FP-CL10B104KA8VPJC_0603-MFG 235.172,38.755 r180 top value=100nF
C131 "06031C101JAT2A" FP-06031C101JAT2A_0603-MFG 233,33 r180 top value=100pF
C132 "CL10B104KA8VPJC" FP-CL10B104KA8VPJC_0603-MFG 235.616,34.322 r270 top value=100nF
C133 "CL10B104KA8VPJC" FP-CL10B104KA8VPJC_0603-MFG 219.245,42 r0 top value=100nF
C134 "C0603C820K5GACTU" 0603 279.3,17.35 r180 top value=82pF
C135 "GMC10X7R104K25NT" FP-GMC10X7R104K25NT_0603-MFG 294.408,15.475 r0 top value=100nF
C136 "C0603C820K5GACTU" 0603 251.404,17.425 r180 top value=82pF
C137 "GMC10X7R104K25NT" FP-GMC10X7R104K25NT_0603-MFG 221.548,21.215 r180 top value=100nF
C138 "GMC10X7R104K25NT" FP-GMC10X7R104K25NT_0603-MFG 267.081,15.65 r0 top value=100nF
C139 "C0603C820K5GACTU" 0603 224.328,19.212 r180 top value=82pF
C140 "GMC10X7R104K25NT" FP-GMC10X7R104K25NT_0603-MFG 239.527,15.675 r0 top value=100nF
C141 "GMC10X7R104K25NT" FP-GMC10X7R104K25NT_0603-MFG 272.957,21.21 r0 top value=100nF
C142 "GMC10X7R104K25NT" FP-GMC10X7R104K25NT_0603-MFG 276.145,21.219 r180 top value=100nF
C143 "GMC10X7R104K25NT" FP-GMC10X7R104K25NT_0603-MFG 245.717,21.475 r0 top value=100nF
C144 "GMC10X7R104K25NT" FP-GMC10X7R104K25NT_0603-MFG 248.849,21.475 r180 top value=100nF
C145 "GMC10X7R104K25NT" FP-GMC10X7R104K25NT_0603-MFG 218.454,21.22 r0 top value=100nF
C146 "CL10B104KA8VPJC" FP-CL10B104KA8VPJC_0603-MFG 282.138,29.205 r270 top value=100nF
C147 "0603ZC100KAT2A" 0603 272.057,23.834 r270 top value=10pF
C148 "0603ZC100KAT2A" 0603 277.363,25.568 r270 top value=10pF
C149 "0603ZC100KAT2A" 0603 244.28,24.145 r270 top value=10pF
C150 "0603ZC100KAT2A" 0603 249.674,25.695 r270 top value=10pF
C151 "0603ZC100KAT2A" 0603 216.849,23.465 r270 top value=10pF
C152 "0603ZC100KAT2A" 0603 222.221,25.41 r270 top value=10pF
C153 "0603ZC100KAT2A" 0603 142.114,10.201 r90 top value=10pF
C154 "0603ZC100KAT2A" 0603 143.764,10.216 r90 top value=10pF
C155 "0603ZC100KAT2A" 0603 145.371,10.18 r90 top value=10pF
C158 "CL10B105KA8VPJC" FP-CL10B105KA8VPJC_0603-MFG 282.287,63.125 r180 top value=1µF
C159 "06033C104KAT2A" 0603 282.292,65 r0 top value=0.1uF
C160 "C1608C0G2A392J080AE" 0603 273.96,63.925 r90 top value=3900pF
C161 "C2220X103KHRAC7800" FP-C2220X103KHRAC7800_2220-MFG 71,63 r180 top value=10nF
C162 "C1608C0G2A392J080AE" 0603 278.895,65.029 r0 top value=3900pF
C163 "C2220X103KHRAC7800" FP-C2220X103KHRAC7800_2220-MFG 193,137 r180 top value=10nF
C164 "C2220X103KHRAC7800" FP-C2220X103KHRAC7800_2220-MFG 192,62 r0 top value=10nF
C165 "C2220X103KHRAC7800" FP-C2220X103KHRAC7800_2220-MFG 78,63 r180 top value=10nF
C166 "C2220X103KHRAC7800" FP-C2220X103KHRAC7800_2220-MFG 16,142 r180 top value=10nF
C167 "C2220X103KHRAC7800" FP-C2220X103KHRAC7800_2220-MFG 63,69 r0 top value=10nF
C168 "C2220X103KHRAC7800" FP-C2220X103KHRAC7800_2220-MFG 61,125 r0 top value=10nF
C169 "EMK212BB7106KG-T" 0805_HV 51,16.406 r270 top value=10uF
C170 "EMK212BB7106KG-T" 0805_HV 48.548,16.406 r270 top value=10uF
C171 "06033C104JAT2A" 0603 46.34,16.46 r90 top value=0.1uF
C172 "C0603C103K4RACTU" 0603 48.548,11.423 r270 top value=0.01uF
C173 "C4ASPBW4250A3MJ" FP-C4ASPBW4250A3MJ_RADIAL-MFG 331,15 r0 bottom value=2.5µF
C174 "C4ASPBW4250A3MJ" FP-C4ASPBW4250A3MJ_RADIAL-MFG 331,49 r0 bottom value=2.5µF
C175 "C4ASPBW4250A3MJ" FP-C4ASPBW4250A3MJ_RADIAL-MFG 331,100 r0 bottom value=2.5µF
C176 "C4ASPBW4250A3MJ" FP-C4ASPBW4250A3MJ_RADIAL-MFG 331,136 r0 bottom value=2.5µF
C177 "C4ASPBW4250A3MJ" FP-C4ASPBW4250A3MJ_RADIAL-MFG 319,172 r0 bottom value=2.5µF
C178 "C4ASPBW4250A3MJ" FP-C4ASPBW4250A3MJ_RADIAL-MFG 319,203 r0 bottom value=2.5µF
C179 "C4ASPBW4250A3MJ" FP-C4ASPBW4250A3MJ_RADIAL-MFG 320,265 r0 bottom value=2.5µF
C180 "C4ASPBW4250A3MJ" FP-C4ASPBW4250A3MJ_RADIAL-MFG 327,234 r0 bottom value=2.5µF
C181 "C2220X103KHRAC7800" FP-C2220X103KHRAC7800_2220-MFG 16,136 r180 top value=10nF
C182 "C2220X103KHRAC7800" FP-C2220X103KHRAC7800_2220-MFG 68,125 r0 top value=10nF
C183 "C2220X103KHRAC7800" FP-C2220X103KHRAC7800_2220-MFG 68,137 r0 top value=10nF
C184 "C2220X103KHRAC7800" FP-C2220X103KHRAC7800_2220-MFG 68,131 r0 top value=10nF
C185 "C2220X103KHRAC7800" FP-C2220X103KHRAC7800_2220-MFG 23,142 r180 top value=10nF
C186 "C2220X103KHRAC7800" FP-C2220X103KHRAC7800_2220-MFG 56,57 r0 top value=10nF
C187 "C2220X103KHRAC7800" FP-C2220X103KHRAC7800_2220-MFG 56,63 r0 top value=10nF
C188 "C2220X103KHRAC7800" FP-C2220X103KHRAC7800_2220-MFG 56,69 r0 top value=10nF
C189 "C2220X103KHRAC7800" FP-C2220X103KHRAC7800_2220-MFG 78,57 r180 top value=10nF
C190 "C2220X103KHRAC7800" FP-C2220X103KHRAC7800_2220-MFG 200,137 r180 top value=10nF
C191 "C2220X103KHRAC7800" FP-C2220X103KHRAC7800_2220-MFG 200,131 r180 top value=10nF
C192 "C2220X103KHRAC7800" FP-C2220X103KHRAC7800_2220-MFG 200,125 r180 top value=10nF
C193 "C2220X103KHRAC7800" FP-C2220X103KHRAC7800_2220-MFG 244,140 r0 top value=10nF
C194 "C2220X103KHRAC7800" FP-C2220X103KHRAC7800_2220-MFG 244,134 r0 top value=10nF
C195 "C2220X103KHRAC7800" FP-C2220X103KHRAC7800_2220-MFG 206,56 r180 top value=10nF
C196 "C2220X103KHRAC7800" FP-C2220X103KHRAC7800_2220-MFG 206,62 r180 top value=10nF
C197 "C2220X103KHRAC7800" FP-C2220X103KHRAC7800_2220-MFG 206,68 r180 top value=10nF
C198 "C2220X103KHRAC7800" FP-C2220X103KHRAC7800_2220-MFG 185,62 r0 top value=10nF
C199 "C2220X103KHRAC7800" FP-C2220X103KHRAC7800_2220-MFG 185,56 r0 top value=10nF
D1 "STTH112A" SMA 79.2,74 r0 top locked value=1200V
D2 "STTH112A" SMA 79.1,115.023 r0 top locked value=1200V
D3 "STTH112A" SMA 182.4,115 r180 top locked value=1200V
D4 "STTH112A" SMA 182.5,73.977 r180 top locked value=1200V
D5 "STTH112A" SMA 84.9,76.677 r90 top locked value=1200V
D6 "STTH112A" SMA 84.6,113.023 r270 top locked value=1200V
D7 "STTH112A" SMA 176.7,112.323 r270 top locked value=1200V
D8 "STTH112A" SMA 177,75.977 r90 top locked value=1200V
D9 "STTH112A" SMA 84.9,84.214 r90 top locked value=1200V
D10 "STTH112A" SMA 84.6,105.16 r270 top locked value=1200V
D11 "STTH112A" SMA 176.7,104.786 r270 top locked value=1200V
D12 "STTH112A" SMA 177,83.84 r90 top locked value=1200V
D13 "STTH112A" SMA 33.1,73.977 r180 top locked value=1200V
D14 "STTH112A" SMA 33,115 r180 top locked value=1200V
D15 "STTH112A" SMA 228.5,115.023 r0 top locked value=1200V
D16 "STTH112A" SMA 228.6,74 r0 top locked value=1200V
D17 "STTH112A" SMA 27.605,78.362 r90 top value=1200V
D18 "STTH112A" SMA 27.3,112.323 r270 top locked value=1200V
D19 "STTH112A" SMA 234,113.023 r270 top locked value=1200V
D20 "STTH112A" SMA 234.3,76.677 r90 top locked value=1200V
D21 "STTH112A" SMA 27.605,86.225 r90 top value=1200V
D22 "STTH112A" SMA 27.3,104.786 r270 top locked value=1200V
D23 "STTH112A" SMA 234,105.16 r270 top locked value=1200V
D24 "STTH112A" SMA 234.3,84.214 r90 top locked value=1200V
D25 "LSL29K-G1H2-1-Z" FP-LSL29K-G1H2-1-Z_0603-0 201.56,22.615 r90 top
D26 "150060VS75000" WL-SMCW_GREEN 197.929,22.615 r90 top value=Green
D27 "150060VS75000" WL-SMCW_GREEN 209.753,22.346 r90 top value=Green
D28 "150060VS75000" WL-SMCW_GREEN 205.713,22.515 r90 top value=Green
D29 "150060VS75000" WL-SMCW_GREEN 66.418,18.08 r270 top value=Green
D30 "B330A-13-F" SMA 69.748,12.716 r270 top value=30V
D31 "150060VS75000" WL-SMCW_GREEN 31.793,18.482 r90 top value=Green
D32 "150060VS75000" WL-SMCW_GREEN 50.275,28.356 r90 top value=Green
D33 "SBR0560S1-7" SOD-123 280.604,37.805 r270 top value=60V
FID1 "Fiducial" Fiducial10-20 264.711,37.237 r0 top
FID2 "Fiducial" Fiducial10-20 14.427,6 r0 top
FID3 "Fiducial" Fiducial10-20 63,6 r180 bottom
H1 "NY PMS 440 0025 PH" "NY PMS 440 0025 PH" 297,76 r0 top
H2 "NY PMS 440 0025 PH" "NY PMS 440 0025 PH" 142.5,219.75 r0 top
H3 "NY PMS 440 0025 PH" "NY PMS 440 0025 PH" 355,212 r0 top
H4 "NY PMS 440 0025 PH" "NY PMS 440 0025 PH" 292,224 r0 top
H5 "NY PMS 440 0025 PH" "NY PMS 440 0025 PH" 249,152 r0 top
H6 "NY PMS 440 0025 PH" "NY PMS 440 0025 PH" 5,5 r0 top
H7 "NY PMS 440 0025 PH" "NY PMS 440 0025 PH" 355,275 r0 top
H8 "NY PMS 440 0025 PH" "NY PMS 440 0025 PH" 340,76 r0 top
H9 "NY PMS 440 0025 PH" "NY PMS 440 0025 PH" 142.552,274.515 r0 top
H10 "NY PMS 440 0025 PH" "NY PMS 440 0025 PH" 9,152 r0 top
H12 "NY PMS 440 0025 PH" "NY PMS 440 0025 PH" 355,162 r0 top
H13 "NY PMS 440 0025 PH" "NY PMS 440 0025 PH" 9,37 r0 top
H14 "NY PMS 440 0025 PH" "NY PMS 440 0025 PH" 129,55 r0 top
H15 "NY PMS 440 0025 PH" "NY PMS 440 0025 PH" 249,37 r0 top
H16 "NY PMS 440 0025 PH" "NY PMS 440 0025 PH" 249.904,100 r0 top
J1 "HLE-103-02-G-DV" Samtec_HLE-103-02-x-DV 77.5,85.5 r270 top locked
J2 "HLE-103-02-G-DV" Samtec_HLE-103-02-x-DV 77.55,103.5 r90 top locked
J3 "HLE-103-02-G-DV" Samtec_HLE-103-02-x-DV 184.1,103.5 r90 top locked
J4 "HLE-103-02-G-DV" Samtec_HLE-103-02-x-DV 184.1,85.5 r270 top locked
J5 "7461086" Wurth_7461086 6,70 r90 top
J6 "7461086" Wurth_7461086 354,76 r90 top
J7 "HLE-103-02-G-DV" Samtec_HLE-103-02-x-DV 34.7,85.5 r270 top locked
J8 "HLE-103-02-G-DV" Samtec_HLE-103-02-x-DV 34.7,103.5 r90 top locked
J9 "HLE-103-02-G-DV" Samtec_HLE-103-02-x-DV 226.9,103.5 r90 top locked
J10 "HLE-103-02-G-DV" Samtec_HLE-103-02-x-DV 226.9,85.5 r270 top locked
J11 "7461086" Wurth_7461086 6,118.323 r90 top
J12 "7461086" Wurth_7461086 354,186 r90 top
J13 "HLE-105-02-G-DV-BE-A" FP-HLE-105-02-G-DV-BE-A_CONN_RCPT_10-MFG 56.15,40.3 r180 top locked
J14 "HLE-105-02-G-DV-BE-A" FP-HLE-105-02-G-DV-BE-A_CONN_RCPT_10-MFG 56.05,148.7 r0 top locked
J15 "HLE-105-02-G-DV-BE-A" FP-HLE-105-02-G-DV-BE-A_CONN_RCPT_10-MFG 205.45,148.7 r0 top locked
J16 "HLE-105-02-G-DV-BE-A" FP-HLE-105-02-G-DV-BE-A_CONN_RCPT_10-MFG 205.55,40.3 r180 top locked
J17 "HSEC8-160-01-L-DV-A-BL" controlCARD-120HSEC 141.604,12.716 r0 bottom locked
J18 "HSEC8-130-01-L-DV-A" controlCARD-180HSEC-60pinAddon 201.315,12.694 r0 bottom locked
J19 "61301011121" Wurth_61301011121 201,2 r180 bottom
J20 "TSM-102-01-T-SV-P-TR" Samtec_TSM-102-01-T-SV-P-TR 60.761,24.301 r180 top
J21 "PJ-002AH-SMT-TR" CUI_PJ-002AH-SMT 92.501,7.034 r90 bottom
J22 "TSM-102-01-T-SV-P-TR" Samtec_TSM-102-01-T-SV-P-TR 60.761,16.886 r180 top
J23 "TSM-102-01-T-SV-P-TR" Samtec_TSM-102-01-T-SV-P-TR 34.352,23.031 r90 top
J24 "HLE-103-02-G-DV" Samtec_HLE-103-02-x-DV 108.5,151.5 r0 top locked
J25 "HLE-103-02-G-DV" Samtec_HLE-103-02-x-DV 156.5,151.5 r0 top
J26 "HLE-103-02-G-DV" Samtec_HLE-103-02-x-DV 100.5,65.5 r0 top locked
J27 "HLE-103-02-G-DV" Samtec_HLE-103-02-x-DV 160.5,65.5 r0 top locked
J28 "0022111031" FP-0022111031_HDR3-MFG 290.5,27.995 r180 bottom
J29 "0022111031" FP-0022111031_HDR3-MFG 290.5,35.55 r180 bottom
L1 "NLFV25T-470K-PF" NLCV25 293.908,18.162 r0 top value=47uH
L2 "NLFV25T-470K-PF" NLCV25 266.77,18.162 r0 top value=47uH
L3 "NLFV25T-470K-PF" NLCV25 239.216,18.159 r0 top value=47uH
L7 "74439324047" FP-74439324047_SMD2-MFG 42.475,20.525 r180 top value=4.7uH
LBL1 "THT-14-423-10" Label_650x200 261,256 r90 bottom
Logo1 "CE Mark" CE_Mark_5mm 36,6 r180 bottom
Logo3 "FCC disclaimer" FCC_disclaimer 362.371,18.096 r90 top
Logo4 "WEEE logo" WEEE_Minimum 27,7 r180 bottom
LOGO6 "CAUTION HOT SURFACE" IEC_HotSurface_Medium 252,249 r0 top
LOGO7 "DANGER HIGH VOLTAGE" IEC_HighVoltage_Medium 235,249 r0 top
MD1 "G4H22MT33GB4" FP-G4H22MT33GB4_SiCPAK-G+_MODIFIED-MFG 56,94.5 r270 bottom locked
MD2 "G4H22MT33GB4" FP-G4H22MT33GB4_SiCPAK-G+_MODIFIED-MFG 205.5,94.5 r90 bottom locked
Q1 "CSD17571Q2" DQK0006C 65.234,21.759 r90 top value=30V
Q2 "DMN3042L-13" FP-DMN3042L-13_SOT23-MFG 279.471,32.855 r0 top
R1 "RC1206FR-07120KL" 1206 32.54,266.75 r90 top value=120k
R2 "RC1206FR-07120KL" 1206 32.54,245.864 r270 top value=120k
R3 "RC1206FR-07120KL" 1206 206.592,268.8 r90 top value=120k
R4 "RC1206FR-07120KL" 1206 206.592,247.971 r270 top value=120k
R5 "RC1206FR-07120KL" 1206 32.54,261.529 r90 top value=120k
R6 "RC1206FR-07120KL" 1206 32.54,240.643 r270 top value=120k
R7 "RC1206FR-07120KL" 1206 206.592,263.593 r90 top value=120k
R8 "RC1206FR-07120KL" 1206 206.592,242.764 r270 top value=120k
R9 "RC1206FR-07120KL" 1206 32.54,256.307 r90 top value=120k
R10 "RC1206FR-07120KL" 1206 32.54,235.421 r270 top value=120k
R11 "RC1206FR-07120KL" 1206 206.592,258.386 r90 top value=120k
R12 "RC1206FR-07120KL" 1206 206.592,237.557 r270 top value=120k
R13 "RC1206FR-07120KL" 1206 32.54,251.086 r90 top value=120k
R14 "RC1206FR-07120KL" 1206 32.54,230.2 r270 top value=120k
R15 "RC1206FR-07120KL" 1206 206.592,253.179 r90 top value=120k
R16 "RC1206FR-07120KL" 1206 206.592,232.35 r270 top value=120k
R17 "ERJ-3EKF1002V" 0603 70.5,88.7 r0 top locked value=10.0k
R18 "ERJ-3EKF1002V" 0603 70.5,100.3 r0 top locked value=10.0k
R19 "ERJ-3EKF1002V" 0603 191.1,100.3 r0 top locked value=10.0k
R20 "ERJ-3EKF1002V" 0603 191.1,88.7 r0 top locked value=10.0k
R21 "RC1206FR-07120KL" 1206 32.54,209.87 r270 top value=120k
R22 "RC1206FR-07120KL" 1206 206.592,210.32 r270 top value=120k
R23 "RC1206FR-07120KL" 1206 32.54,187.659 r90 top value=120k
R24 "RC1206FR-07120KL" 1206 206.592,187.851 r90 top value=120k
R25 "RC1206FR-07120KL" 1206 32.54,204.317 r270 top value=120k
R26 "ERJ-3EKF1002V" 0603 41.7,88.7 r180 top locked value=10.0k
R27 "ERJ-3EKF1002V" 0603 41.7,100.3 r180 top locked value=10.0k
R28 "RC1206FR-07120KL" 1206 206.592,204.703 r270 top value=120k
R29 "ERJ-3EKF1002V" 0603 219.9,100.3 r180 top locked value=10.0k
R30 "ERJ-3EKF1002V" 0603 219.9,88.7 r180 top locked value=10.0k
R31 "RC1206FR-07120KL" 1206 32.54,182.106 r90 top value=120k
R32 "RC1206FR-07120KL" 1206 206.592,182.234 r90 top value=120k
R33 "RC1206FR-07120KL" 1206 32.54,198.764 r270 top value=120k
R34 "RC1206FR-07120KL" 1206 206.592,199.086 r270 top value=120k
R35 "RC1206FR-07120KL" 1206 32.54,176.553 r90 top value=120k
R36 "RC1206FR-07120KL" 1206 206.592,176.617 r90 top value=120k
R37 "RC1206FR-07120KL" 1206 32.54,193.211 r270 top value=120k
R38 "RC1206FR-07120KL" 1206 206.592,193.469 r270 top value=120k
R39 "RC1206FR-07120KL" 1206 32.54,171 r90 top value=120k
R40 "RC1206FR-07120KL" 1206 206.592,171 r90 top value=120k
R41 "WSL4026L5000FEB" WSL4026_0p5milli 133.366,159.313 r180 top locked value=0.0005
R42 "WSL4026L5000FEB" WSL4026_0p5milli 17.625,70 r180 top value=0.0005
R43 "WSL4026L5000FEB" WSL4026_0p5milli 255.375,77.253 r180 top locked value=0.0005
R44 "ERJ-3GEYJ470V" 0603 119.25,23.87 r270 bottom value=47
R45 "ERJ-3EKF1002V" 0603 210.07,16.758 r90 top value=10.0k
R46 "ERJ-3EKF1002V" 0603 206.502,16.994 r90 top value=10.0k
R47 "ERJ-3EKF1002V" 0603 202.541,16.994 r90 top value=10.0k
R48 "CRCW0603499RFKEAC" 0603 197.929,25.619 r90 top value=499
R49 "CRCW0603499RFKEAC" 0603 201.51,25.619 r90 top value=499
R50 "CRCW0603499RFKEAC" 0603 209.753,25.344 r90 top value=499
R51 "ERJ-3GEYJ470V" 0603 121.2,23.87 r270 bottom value=47
R52 "CRCW0603499RFKEAC" 0603 204.932,25.628 r90 top value=499
R53 "ERJ-3EKF1002V" 0603 210.07,12.994 r90 top value=10.0k
R54 "ERJ-3EKF1002V" 0603 206.502,12.994 r90 top value=10.0k
R55 "ERJ-3EKF1002V" 0603 202.541,12.994 r90 top value=10.0k
R56 "ERJ-3GEYJ470V" 0603 123.15,23.87 r270 bottom value=47
R57 "ERJ-3GEYJ470V" 0603 147.033,10.194 r90 top value=47
R58 "ERJ-H3G0R00V" FP-ERJ-H3G0R00V_0603-MFG 134.703,19.719 r270 bottom value=0
R59 "ERJ-H3G0R00V" FP-ERJ-H3G0R00V_0603-MFG 134.89,5.82 r270 bottom value=0
R60 "ERJ-H3G0R00V" FP-ERJ-H3G0R00V_0603-MFG 136.303,19.719 r270 bottom value=0
R61 "ERJ-H3G0R00V" FP-ERJ-H3G0R00V_0603-MFG 136.503,5.82 r270 bottom value=0
R62 "ERJ-H3G0R00V" FP-ERJ-H3G0R00V_0603-MFG 137.903,19.719 r270 bottom value=0
R63 "ERJ-H3G0R00V" FP-ERJ-H3G0R00V_0603-MFG 138.116,5.82 r270 bottom value=0
R64 "ERJ-H3G0R00V" FP-ERJ-H3G0R00V_0603-MFG 86,27 r270 top value=0
R65 "ERJ-H3G0R00V" FP-ERJ-H3G0R00V_0603-MFG 139.503,19.719 r270 bottom value=0
R66 "ERJ-H3G0R00V" FP-ERJ-H3G0R00V_0603-MFG 139.728,5.82 r270 bottom value=0
R67 "ERJ-3GEYJ470V" 0603 125.1,23.87 r270 bottom value=47
R68 "ERJ-3GEYJ470V" 0603 148.647,10.194 r90 top value=47
R69 "ERJ-H3G0R00V" FP-ERJ-H3G0R00V_0603-MFG 141.374,5.869 r270 bottom value=0
R70 "ERJ-H3G0R00V" FP-ERJ-H3G0R00V_0603-MFG 141.077,19.769 r270 bottom value=0
R71 "ERJ-H3G0R00V" FP-ERJ-H3G0R00V_0603-MFG 142.799,5.869 r270 bottom value=0
R72 "ERJ-H3G0R00V" FP-ERJ-H3G0R00V_0603-MFG 142.521,19.769 r270 bottom value=0
R73 "ERJ-H3G0R00V" FP-ERJ-H3G0R00V_0603-MFG 144.286,5.869 r270 bottom value=0
R74 "ERJ-H3G0R00V" FP-ERJ-H3G0R00V_0603-MFG 145.836,5.869 r270 bottom value=0
R75 "ERJ-3GEYJ470V" 0603 92.276,16.234 r270 top value=47
R76 "ERJ-3GEYJ470V" 0603 97.63,16.234 r270 top value=47
R77 "ERJ-3GEYJ470V" 0603 127.05,23.87 r270 bottom value=47
R78 "ERJ-3GEYJ470V" 0603 150.37,10.194 r90 top value=47
R79 "ERJ-H3G0R00V" FP-ERJ-H3G0R00V_0603-MFG 150.722,19.719 r270 bottom value=0
R80 "ERJ-3GEYJ470V" 0603 99.141,29.384 r90 top value=47
R81 "ERJ-H3G0R00V" FP-ERJ-H3G0R00V_0603-MFG 152.28,19.719 r270 bottom value=0
R82 "ERJ-H3G0R00V" FP-ERJ-H3G0R00V_0603-MFG 153.839,19.719 r270 bottom value=0
R83 "ERJ-H3G0R00V" FP-ERJ-H3G0R00V_0603-MFG 155.397,19.719 r270 bottom value=0
R84 "ERJ-3GEYJ470V" 0603 93.964,29.384 r90 top value=47
R85 "ERJ-3GEYJ470V" 0603 129,23.87 r270 bottom value=47
R86 "ERJ-3GEYJ470V" 0603 151.97,10.194 r90 top value=47
R87 "ERJ-H3G0R00V" FP-ERJ-H3G0R00V_0603-MFG 156.955,19.719 r270 bottom value=0
R88 "ERJ-H3G0R00V" FP-ERJ-H3G0R00V_0603-MFG 158.514,19.719 r270 bottom value=0
R89 "ERJ-3EKF1002V" 0603 94.021,16.234 r90 top value=10.0k
R90 "ERJ-H3G0R00V" FP-ERJ-H3G0R00V_0603-MFG 160.072,19.719 r270 bottom value=0
R91 "ERJ-3EKF1002V" 0603 88.546,16.234 r90 top value=10.0k
R92 "ERJ-3EKF1002V" 0603 97.489,29.384 r270 top value=10.0k
R93 "ERJ-3EKF1002V" 0603 90.392,29.409 r270 top value=10.0k
R94 "ERJ-3GEYJ470V" 0603 153.839,10.169 r90 top value=47
R95 "ERJ-H3G0R00V" FP-ERJ-H3G0R00V_0603-MFG 161.63,19.719 r270 bottom value=0
R96 "ERJ-H3G0R00V" FP-ERJ-H3G0R00V_0603-MFG 158.422,5.869 r90 bottom value=0
R97 "ERJ-3GEYJ470V" 0603 144.164,19.898 r270 top value=47
R98 "ERJ-H3G0R00V" FP-ERJ-H3G0R00V_0603-MFG 163.188,19.719 r270 bottom value=0
R99 "ERJ-H3G0R00V" FP-ERJ-H3G0R00V_0603-MFG 159.897,5.869 r90 bottom value=0
R100 "ERJ-H3G0R00V" FP-ERJ-H3G0R00V_0603-MFG 164.747,19.919 r270 bottom value=0
R101 "ERJ-H3G0R00V" FP-ERJ-H3G0R00V_0603-MFG 161.522,5.869 r90 bottom value=0
R102 "ERJ-H3G0R00V" FP-ERJ-H3G0R00V_0603-MFG 166.305,19.919 r270 bottom value=0
R103 "ERJ-H3G0R00V" FP-ERJ-H3G0R00V_0603-MFG 163.222,5.869 r90 bottom value=0
R104 "ERJ-H3G0R00V" FP-ERJ-H3G0R00V_0603-MFG 153.763,41.125 r270 top value=0
R105 "ERJ-H3G0R00V" FP-ERJ-H3G0R00V_0603-MFG 167.863,19.919 r270 bottom value=0
R106 "ERJ-H3G0R00V" FP-ERJ-H3G0R00V_0603-MFG 164.822,5.869 r90 bottom value=0
R107 "ERJ-H3G0R00V" FP-ERJ-H3G0R00V_0603-MFG 169.422,19.719 r270 bottom value=0
R108 "ERJ-H3G0R00V" FP-ERJ-H3G0R00V_0603-MFG 166.422,5.869 r90 bottom value=0
R109 "ERJ-3GEYJ470V" 0603 155.572,10.169 r90 top value=47
R110 "ERJ-3GEYJ470V" 0603 145.836,19.898 r270 top value=47
R111 "ERJ-3GEYJ470V" 0603 145.67,50.075 r90 top value=47
R112 "ERJ-3GEYJ470V" 0603 140.516,50.075 r90 top value=47
R113 "ERJ-3GEYJ470V" 0603 147.508,19.898 r270 top value=47
R114 "ERJ-3GEYJ470V" 0603 140.399,36.075 r270 top value=47
R115 "ERJ-3GEYJ470V" 0603 191.315,19.432 r270 bottom value=47
R116 "ERJ-H3G0R00V" FP-ERJ-H3G0R00V_0603-MFG 191.315,5.919 r90 bottom value=0
R117 "ERJ-3GEYJ470V" 0603 145.553,36.075 r270 top value=47
R118 "ERJ-3GEYJ470V" 0603 193.522,5.844 r270 bottom value=47
R119 "ERJ-H3G0R00V" FP-ERJ-H3G0R00V_0603-IPC_B 193.815,19.432 r90 bottom value=0
R120 "ERJ-3EKF1002V" 0603 143.951,50.075 r270 top value=10.0k
R121 "ERJ-3EKF1002V" 0603 149.105,50.075 r270 top value=10.0k
R122 "ERJ-3EKF1002V" 0603 143.835,36.075 r90 top value=10.0k
R123 "ERJ-3EKF1002V" 0603 148.989,36.075 r90 top value=10.0k
R124 "ERJ-3GEYJ470V" 0603 149.18,19.898 r270 top value=47
R125 "ERJ-H3G0R00V" FP-ERJ-H3G0R00V_0603-MFG 203.922,19.382 r90 bottom value=0
R126 "ERJ-H3G0R00V" FP-ERJ-H3G0R00V_0603-MFG 204.097,5.919 r90 bottom value=0
R127 "ERJ-H3G0R00V" FP-ERJ-H3G0R00V_0603-MFG 205.322,19.382 r90 bottom value=0
R128 "ERJ-H3G0R00V" FP-ERJ-H3G0R00V_0603-MFG 205.497,5.919 r90 bottom value=0
R129 "ERJ-H3G0R00V" FP-ERJ-H3G0R00V_0603-MFG 206.722,19.382 r90 bottom value=0
R130 "ERJ-H3G0R00V" FP-ERJ-H3G0R00V_0603-MFG 206.897,5.919 r90 bottom value=0
R131 "ERJ-H3G0R00V" FP-ERJ-H3G0R00V_0603-MFG 208.122,19.382 r90 bottom value=0
R132 "ERJ-H3G0R00V" FP-ERJ-H3G0R00V_0603-MFG 208.297,5.919 r90 bottom value=0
